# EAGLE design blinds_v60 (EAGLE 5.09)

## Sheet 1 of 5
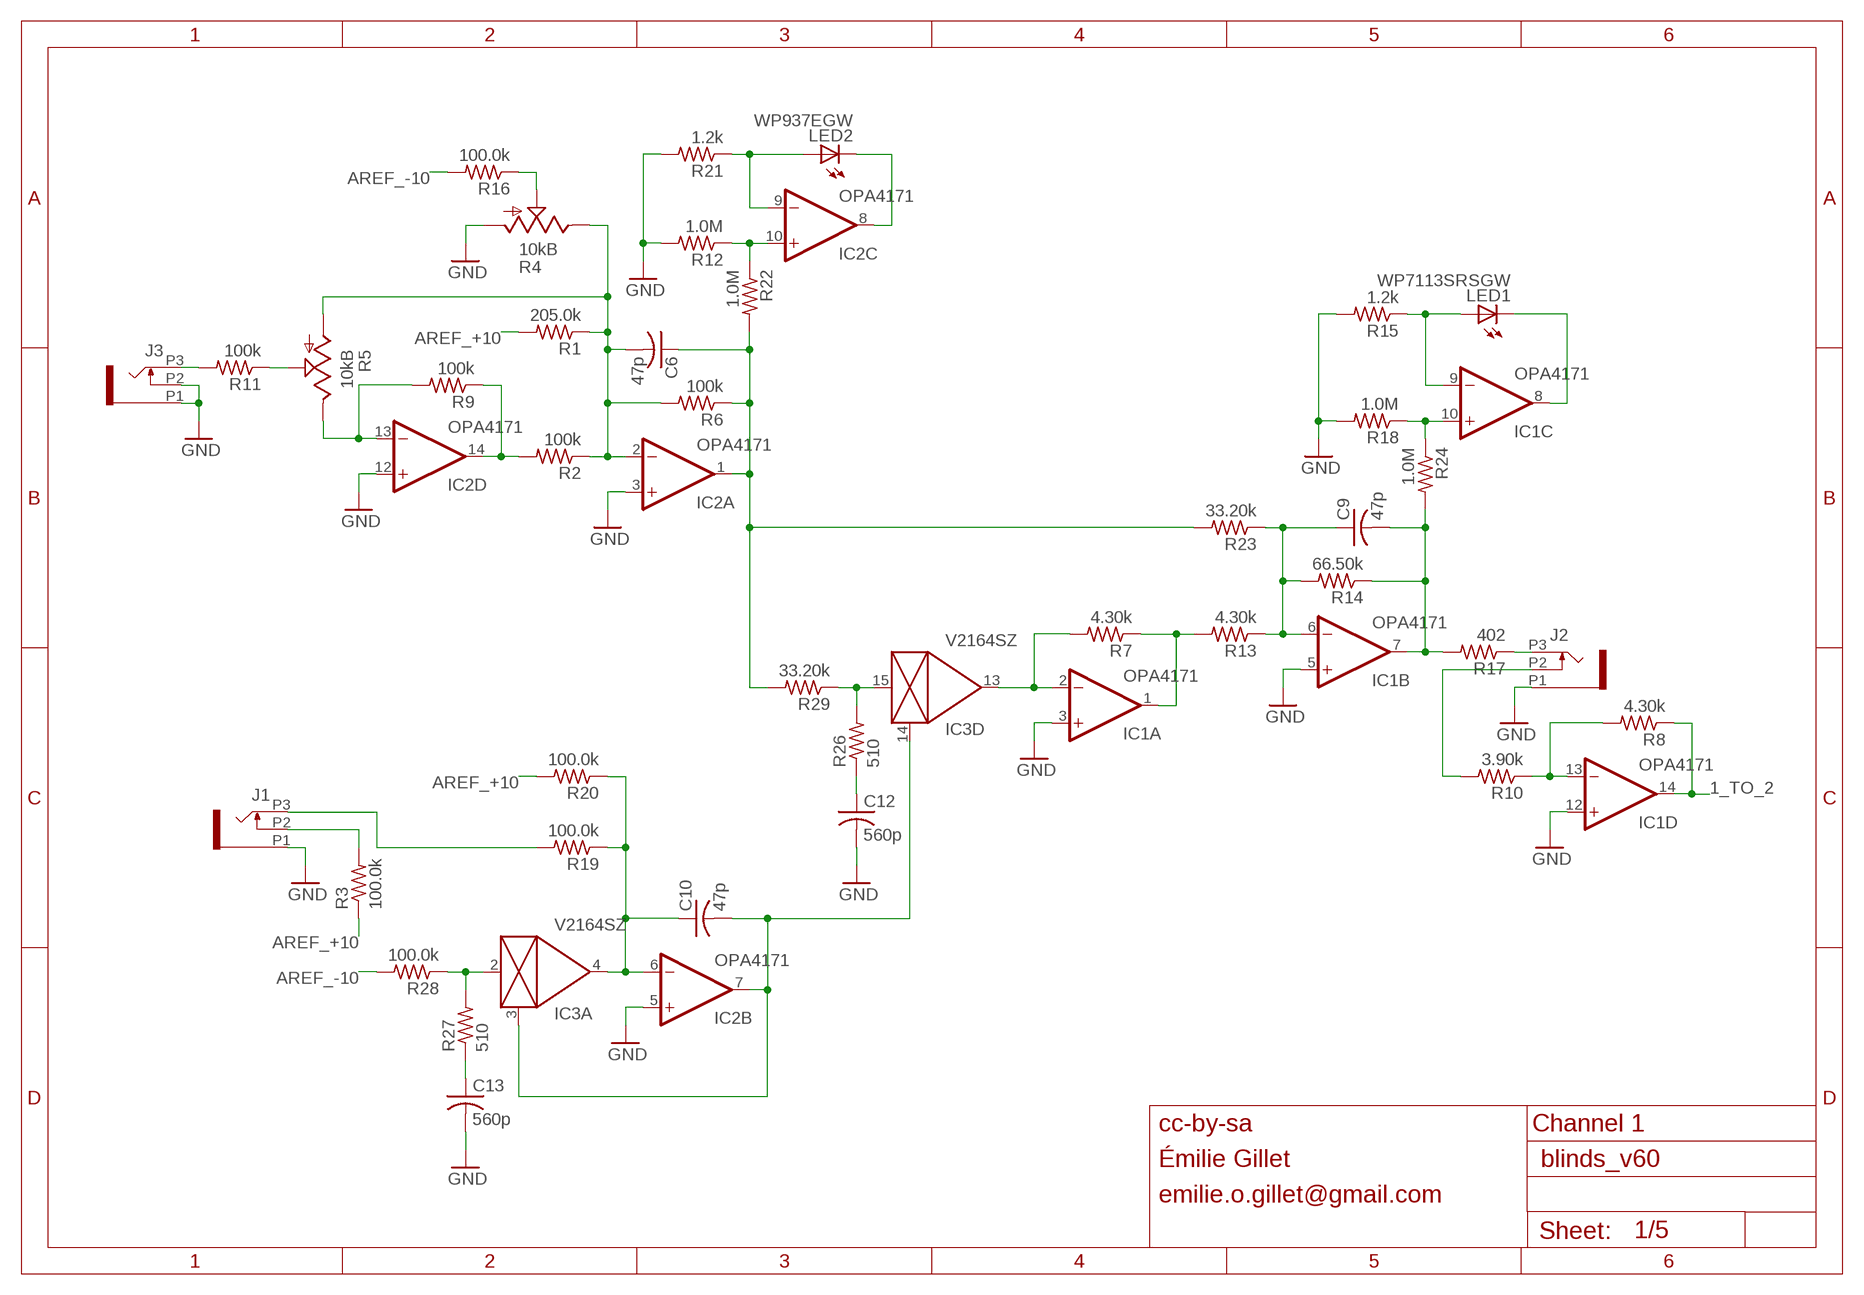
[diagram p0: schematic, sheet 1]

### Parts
C6  47p  C-USC0603  [C0603]
C9  47p  C-USC0603  [C0603]
C10  47p  C-USC0603  [C0603]
C12  560p  C-USC0603  [C0603]
C13  560p  C-USC0603  [C0603]
IC1  OPA4171  TL074PW  [TSSOP14]
IC2  OPA4171  TL074PW  [TSSOP14]
IC3  V2164SZ  SSM2164S  [SOIC16N]
J1  PJ301_THONKICONN6  [WQP_PJ_301M6]
J2  PJ301_THONKICONN6  [WQP_PJ_301M6]
J3  PJ301_THONKICONN6  [WQP_PJ_301M6]
LED1  WP7113SRSGW  LED5MM  [LED5MM]
LED2  WP937EGW  LED3MM  [LED3MM]
R1  205.0k  R-US_R0603  [R0603]
R2  100k  R-US_R0603  [R0603]
R3  100.0k  R-US_R0603  [R0603]
R4  10kB  POT_USVERTICAL_PS  [ALPS_POT_VERTICAL_PS]
R5  10kB  POT_USVERTICAL  [ALPS_POT_VERTICAL]
R6  100k  R-US_R0603  [R0603]
R7  4.30k  R-US_R0603  [R0603]
R8  4.30k  R-US_R0603  [R0603]
R9  100k  R-US_R0603  [R0603]
R10  3.90k  R-US_R0603  [R0603]
R11  100k  R-US_R0603  [R0603]
R12  1.0M  R-US_R0603  [R0603]
R13  4.30k  R-US_R0603  [R0603]
R14  66.50k  R-US_R0603  [R0603]
R15  1.2k  R-US_R0603  [R0603]
R16  100.0k  R-US_R0603  [R0603]
R17  402  R-US_R0603  [R0603]
R18  1.0M  R-US_R0603  [R0603]
R19  100.0k  R-US_R0603  [R0603]
R20  100.0k  R-US_R0603  [R0603]
R21  1.2k  R-US_R0603  [R0603]
R22  1.0M  R-US_R0603  [R0603]
R23  33.20k  R-US_R0603  [R0603]
R24  1.0M  R-US_R0603  [R0603]
R26  510  R-US_R0603  [R0603]
R27  510  R-US_R0603  [R0603]
R28  100.0k  R-US_R0603  [R0603]
R29  33.20k  R-US_R0603  [R0603]

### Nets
1_TO_2: IC1.14(D:OUT) R8.1 ; also sheet 2
AREF_+10: R1.2 R3.1 R20.2 ; also sheet 2,3,4,5
AREF_-10: R16.2 R28.2 ; also sheet 2,3,4,5
CV_IN_1: J3.P3 R11.2
FOO: IC3.2(A:IN) R27.2 R28.1
GAIN_1: C6.1 IC2.1(A:OUT) R6.1 R22.2 R23.2 R29.2
GND: C12.2 C13.2 IC1.3(A:+IN) IC1.5(B:+IN) IC1.12(D:+IN) IC2.3(A:+IN) IC2.5(B:+IN) IC2.12(D:+IN) J1.P1 J2.P1 J3.P1 J3.P2 R4.P$3(A) R12.2 R15.2 R18.2 R21.2 ; also sheet 2,3,4,5
N$2: R4.P$2(S) R16.1
N$3: IC1.2(A:-IN) IC3.13(D:OUT) R7.2
N$4: IC2.8(C:OUT) LED2.K(C)
N$5: IC2.13(D:-IN) R5.P$1(E) R9.2
N$7: J2.P3 R17.1
N$8: IC2.14(D:OUT) R2.2 R9.1
N$9: C6.2 IC2.2(A:-IN) R1.1 R2.1 R4.P$1(E) R5.P$3(A) R6.2
N$10: C9.1 IC1.6(B:-IN) R13.1 R14.2 R23.1
N$14: R5.P$2(S) R11.1
N$15: IC2.9(C:-IN) LED2.A R21.1
N$18: IC1.8(C:OUT) LED1.K(C)
N$19: IC1.9(C:-IN) LED1.A R15.1
N$20: C13.1 R27.1
N$21: J1.P3 R19.2
N$22: IC1.13(D:-IN) R8.2 R10.1
N$25: J2.P2 R10.2
N$47: C12.1 R26.1
N$54: J1.P2 R3.2
N$64: IC1.1(A:OUT) R7.1 R13.2
N$65: C10.1 IC2.6(B:-IN) IC3.4(A:OUT) R19.1 R20.1
N$66: C10.2 IC2.7(B:OUT) IC3.3(A:CTRL) IC3.14(D:CTRL)
N$75: IC3.15(D:IN) R26.2 R29.1
N$96: IC1.10(C:+IN) R18.1 R24.1
N$99: IC2.10(C:+IN) R12.1 R22.1
OUT1: C9.2 IC1.7(B:OUT) R14.1 R17.2 R24.2

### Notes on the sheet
- cc-by-sa | Channel 1
- Émilie Gillet
- emilie.o.gillet@gmail.com

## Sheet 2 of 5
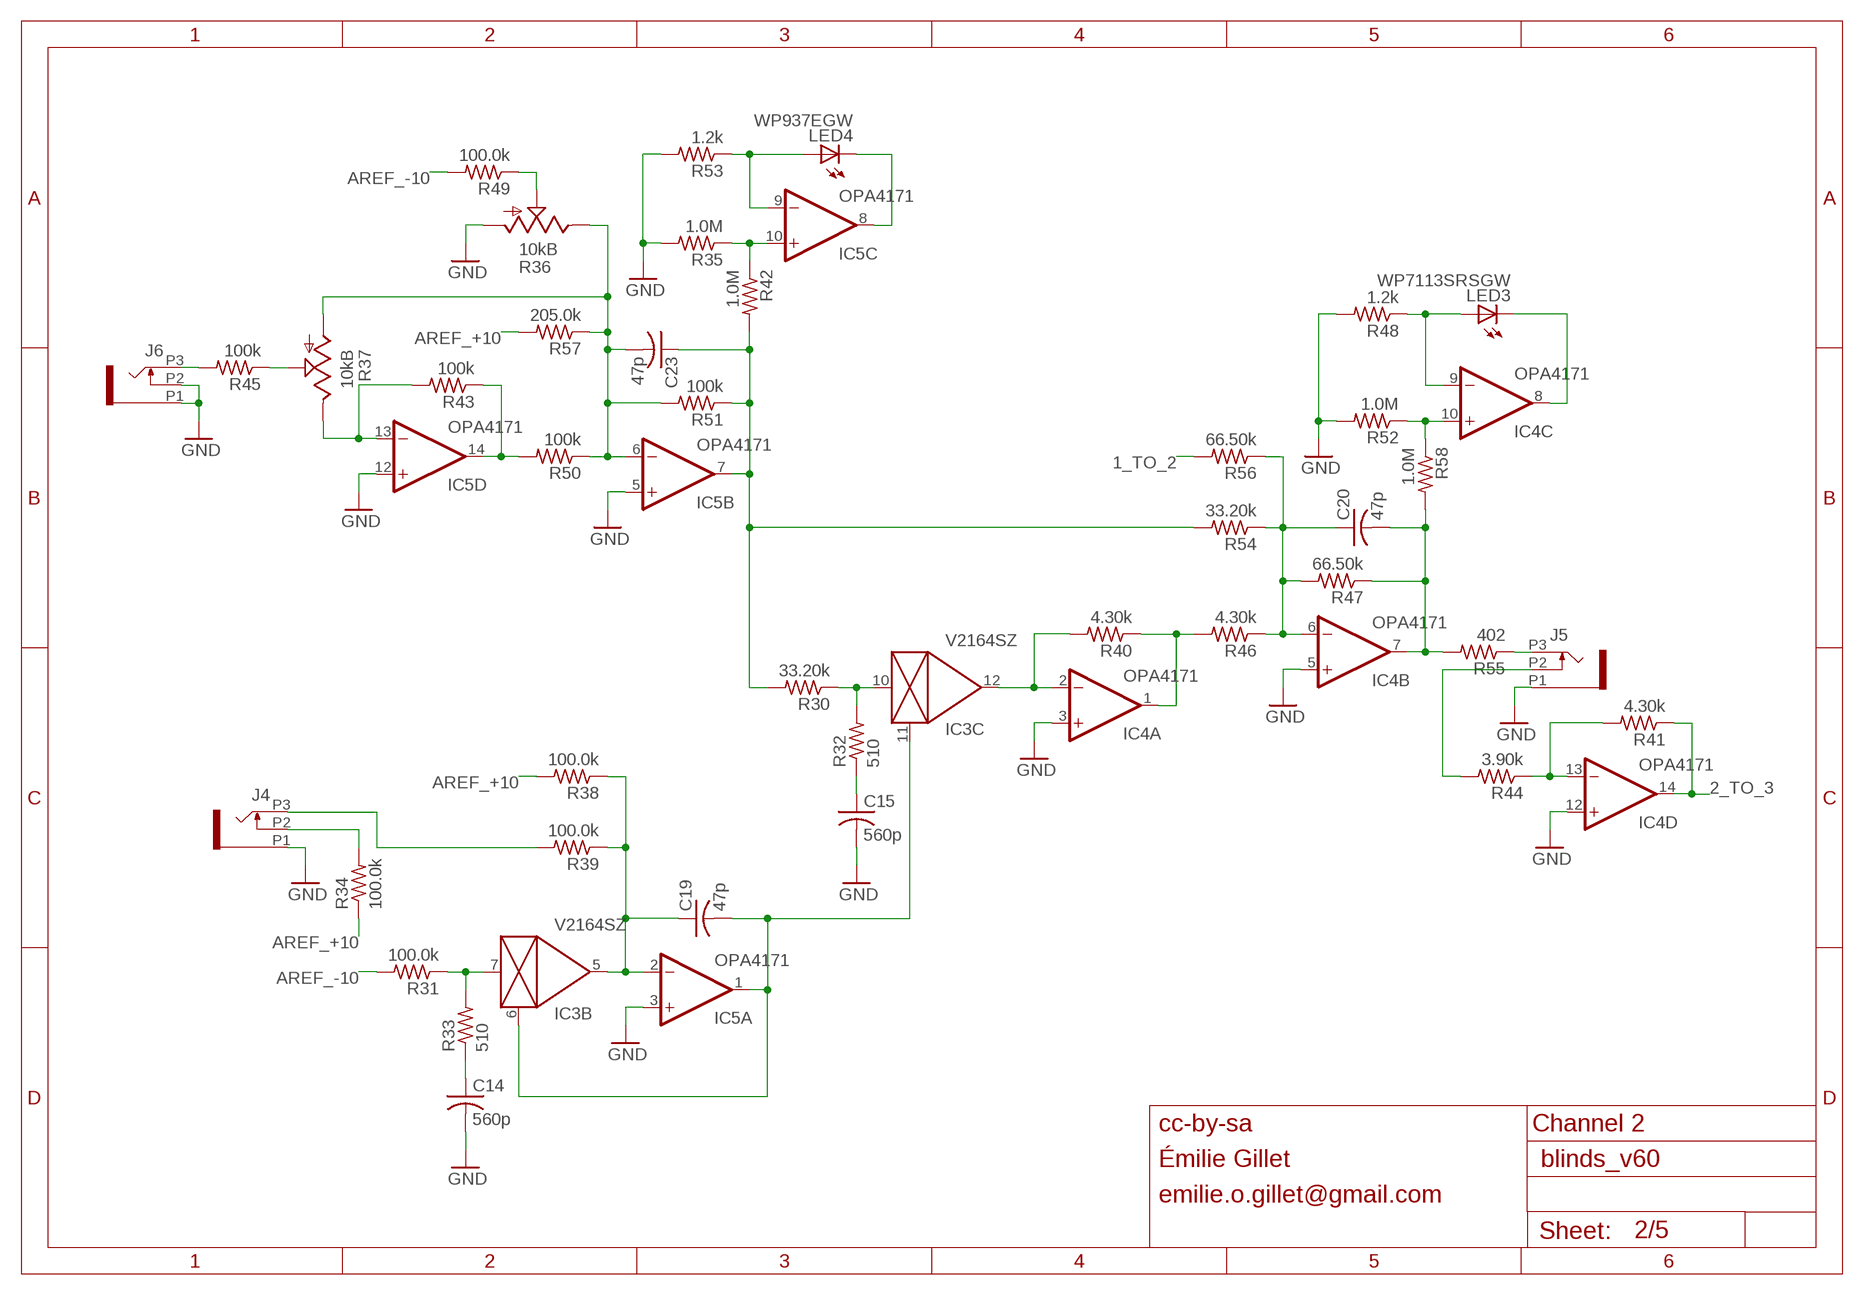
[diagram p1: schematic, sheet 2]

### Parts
C14  560p  C-USC0603  [C0603]
C15  560p  C-USC0603  [C0603]
C19  47p  C-USC0603  [C0603]
C20  47p  C-USC0603  [C0603]
C23  47p  C-USC0603  [C0603]
IC4  OPA4171  TL074PW  [TSSOP14]
IC5  OPA4171  TL074PW  [TSSOP14]
J4  PJ301_THONKICONN6  [WQP_PJ_301M6]
J5  PJ301_THONKICONN6  [WQP_PJ_301M6]
J6  PJ301_THONKICONN6  [WQP_PJ_301M6]
LED3  WP7113SRSGW  LED5MM  [LED5MM]
LED4  WP937EGW  LED3MM  [LED3MM]
R30  33.20k  R-US_R0603  [R0603]
R31  100.0k  R-US_R0603  [R0603]
R32  510  R-US_R0603  [R0603]
R33  510  R-US_R0603  [R0603]
R34  100.0k  R-US_R0603  [R0603]
R35  1.0M  R-US_R0603  [R0603]
R36  10kB  POT_USVERTICAL_PS  [ALPS_POT_VERTICAL_PS]
R37  10kB  POT_USVERTICAL  [ALPS_POT_VERTICAL]
R38  100.0k  R-US_R0603  [R0603]
R39  100.0k  R-US_R0603  [R0603]
R40  4.30k  R-US_R0603  [R0603]
R41  4.30k  R-US_R0603  [R0603]
R42  1.0M  R-US_R0603  [R0603]
R43  100k  R-US_R0603  [R0603]
R44  3.90k  R-US_R0603  [R0603]
R45  100k  R-US_R0603  [R0603]
R46  4.30k  R-US_R0603  [R0603]
R47  66.50k  R-US_R0603  [R0603]
R48  1.2k  R-US_R0603  [R0603]
R49  100.0k  R-US_R0603  [R0603]
R50  100k  R-US_R0603  [R0603]
R51  100k  R-US_R0603  [R0603]
R52  1.0M  R-US_R0603  [R0603]
R53  1.2k  R-US_R0603  [R0603]
R54  33.20k  R-US_R0603  [R0603]
R55  402  R-US_R0603  [R0603]
R56  66.50k  R-US_R0603  [R0603]
R57  205.0k  R-US_R0603  [R0603]
R58  1.0M  R-US_R0603  [R0603]

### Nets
1_TO_2: R56.2 ; also sheet 1
2_TO_3: IC4.14(D:OUT) R41.1 ; also sheet 3
AREF_+10: R34.1 R38.2 R57.2 ; also sheet 1,3,4,5
AREF_-10: R31.2 R49.2 ; also sheet 1,3,4,5
FOO1: IC3.7(B:IN) R31.1 R33.2
GAIN_2: C23.1 IC5.7(B:OUT) R30.2 R42.2 R51.1 R54.2
GND: C14.2 C15.2 IC4.3(A:+IN) IC4.5(B:+IN) IC4.12(D:+IN) IC5.3(A:+IN) IC5.5(B:+IN) IC5.12(D:+IN) J4.P1 J5.P1 J6.P1 J6.P2 R35.2 R36.P$3(A) R48.2 R52.2 R53.2 ; also sheet 1,3,4,5
N$6: J5.P3 R55.1
N$17: C15.1 R32.1
N$24: IC3.10(C:IN) R30.1 R32.2
N$26: IC3.12(C:OUT) IC4.2(A:-IN) R40.2
N$27: C20.1 IC4.6(B:-IN) R46.1 R47.2 R54.1 R56.1
N$28: J6.P3 R45.2
N$29: IC5.13(D:-IN) R37.P$1(E) R43.2
N$30: IC5.14(D:OUT) R43.1 R50.2
N$31: C23.2 IC5.6(B:-IN) R36.P$1(E) R37.P$3(A) R50.1 R51.2 R57.1
N$32: R36.P$2(S) R49.1
N$33: IC5.8(C:OUT) LED4.K(C)
N$34: IC5.9(C:-IN) LED4.A R53.1
N$35: IC4.8(C:OUT) LED3.K(C)
N$36: IC4.9(C:-IN) LED3.A R48.1
N$37: IC4.13(D:-IN) R41.2 R44.1
N$38: J5.P2 R44.2
N$39: IC4.1(A:OUT) R40.1 R46.2
N$40: R37.P$2(S) R45.1
N$41: C14.1 R33.1
N$42: C19.1 IC3.5(B:OUT) IC5.2(A:-IN) R38.1 R39.1
N$43: C19.2 IC3.6(B:CTRL) IC3.11(C:CTRL) IC5.1(A:OUT)
N$44: J4.P3 R39.2
N$87: J4.P2 R34.2
N$97: IC4.10(C:+IN) R52.1 R58.1
N$103: IC5.10(C:+IN) R35.1 R42.1
OUT2: C20.2 IC4.7(B:OUT) R47.1 R55.2 R58.2

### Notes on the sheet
- cc-by-sa | Channel 2
- Émilie Gillet
- emilie.o.gillet@gmail.com

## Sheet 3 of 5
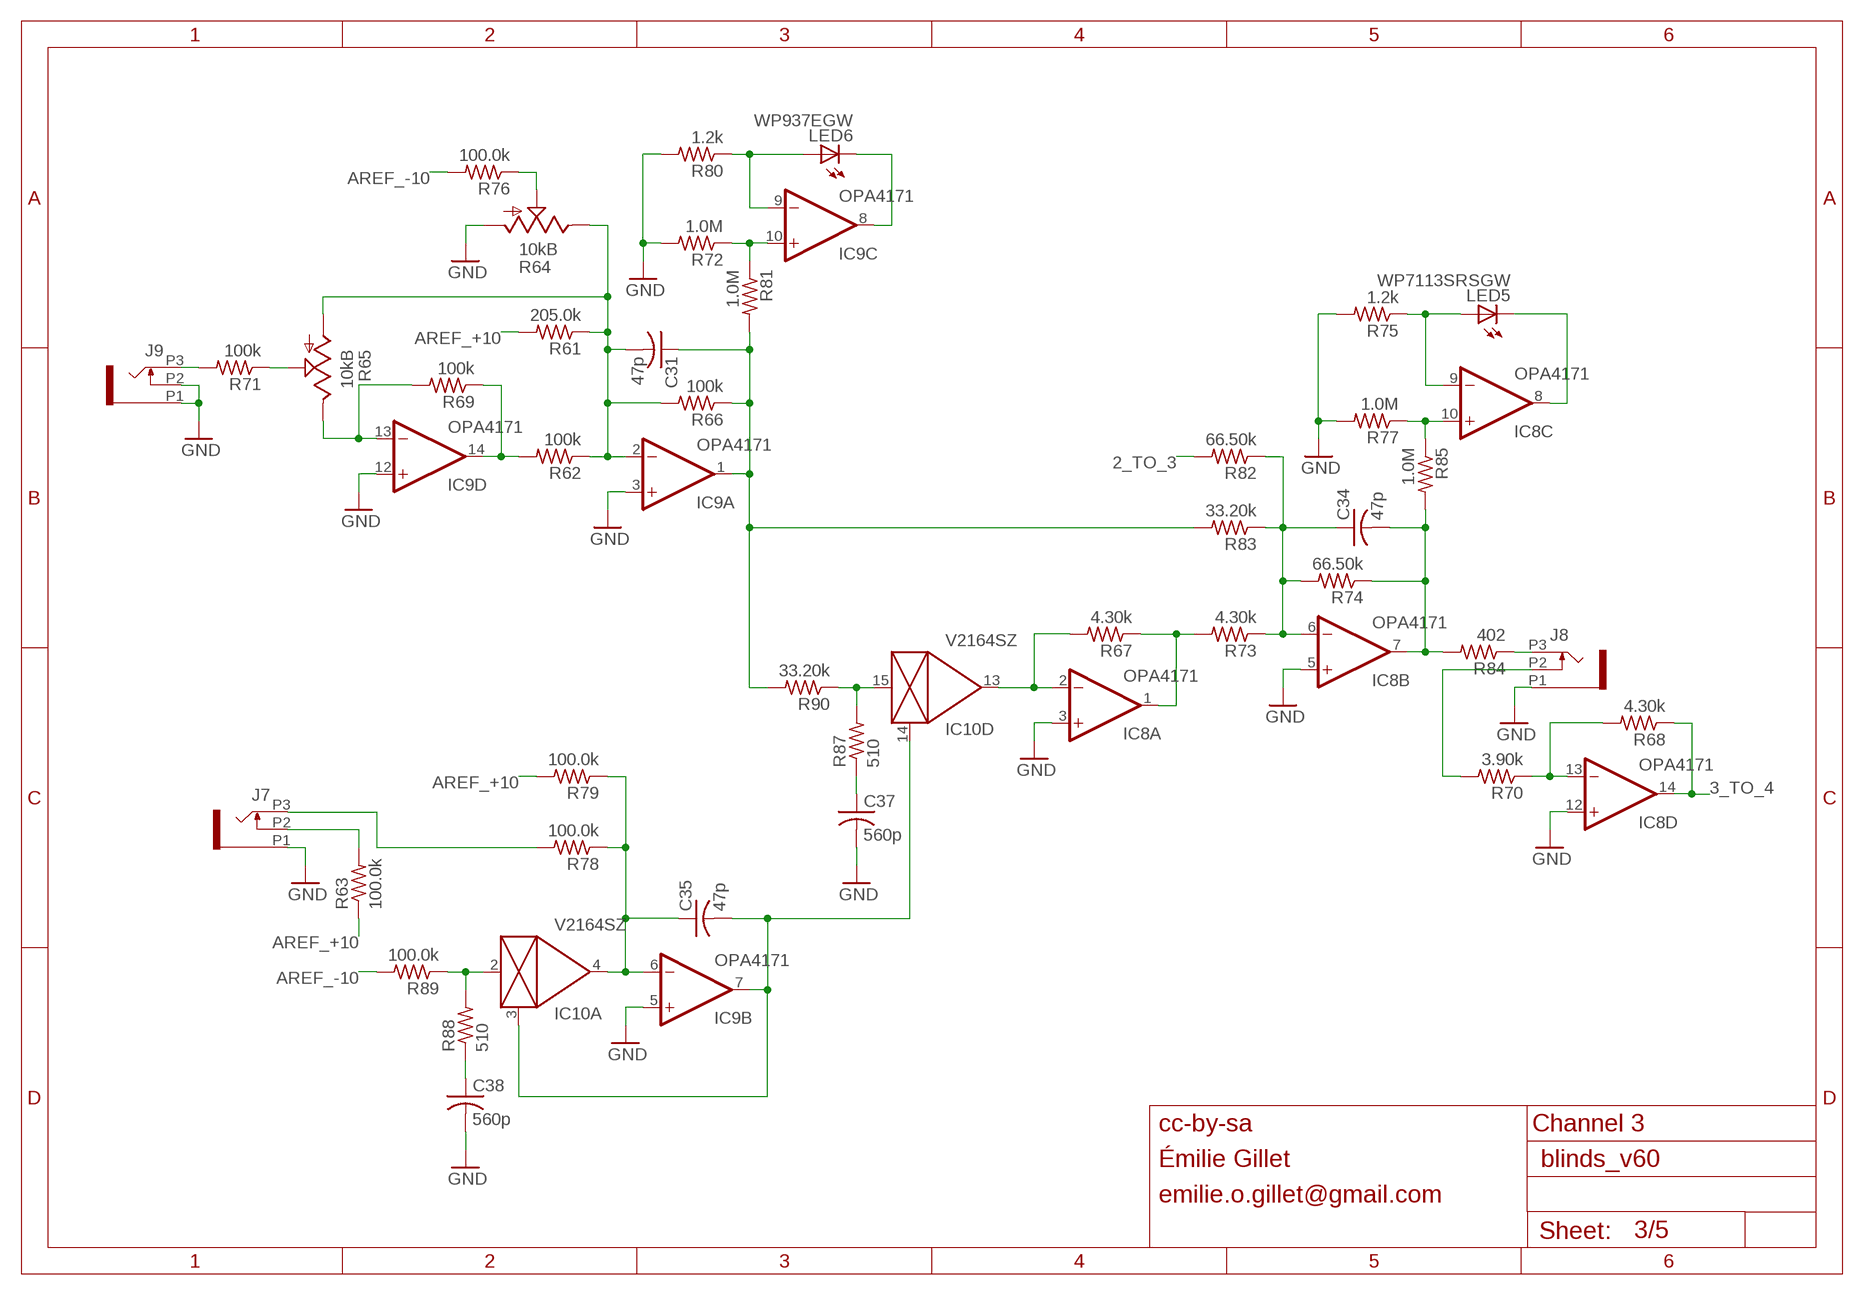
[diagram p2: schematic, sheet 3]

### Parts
C31  47p  C-USC0603  [C0603]
C34  47p  C-USC0603  [C0603]
C35  47p  C-USC0603  [C0603]
C37  560p  C-USC0603  [C0603]
C38  560p  C-USC0603  [C0603]
IC8  OPA4171  TL074PW  [TSSOP14]
IC9  OPA4171  TL074PW  [TSSOP14]
IC10  V2164SZ  SSM2164S  [SOIC16N]
J7  PJ301_THONKICONN6  [WQP_PJ_301M6]
J8  PJ301_THONKICONN6  [WQP_PJ_301M6]
J9  PJ301_THONKICONN6  [WQP_PJ_301M6]
LED5  WP7113SRSGW  LED5MM  [LED5MM]
LED6  WP937EGW  LED3MM  [LED3MM]
R61  205.0k  R-US_R0603  [R0603]
R62  100k  R-US_R0603  [R0603]
R63  100.0k  R-US_R0603  [R0603]
R64  10kB  POT_USVERTICAL_PS  [ALPS_POT_VERTICAL_PS]
R65  10kB  POT_USVERTICAL  [ALPS_POT_VERTICAL]
R66  100k  R-US_R0603  [R0603]
R67  4.30k  R-US_R0603  [R0603]
R68  4.30k  R-US_R0603  [R0603]
R69  100k  R-US_R0603  [R0603]
R70  3.90k  R-US_R0603  [R0603]
R71  100k  R-US_R0603  [R0603]
R72  1.0M  R-US_R0603  [R0603]
R73  4.30k  R-US_R0603  [R0603]
R74  66.50k  R-US_R0603  [R0603]
R75  1.2k  R-US_R0603  [R0603]
R76  100.0k  R-US_R0603  [R0603]
R77  1.0M  R-US_R0603  [R0603]
R78  100.0k  R-US_R0603  [R0603]
R79  100.0k  R-US_R0603  [R0603]
R80  1.2k  R-US_R0603  [R0603]
R81  1.0M  R-US_R0603  [R0603]
R82  66.50k  R-US_R0603  [R0603]
R83  33.20k  R-US_R0603  [R0603]
R84  402  R-US_R0603  [R0603]
R85  1.0M  R-US_R0603  [R0603]
R87  510  R-US_R0603  [R0603]
R88  510  R-US_R0603  [R0603]
R89  100.0k  R-US_R0603  [R0603]
R90  33.20k  R-US_R0603  [R0603]

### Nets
2_TO_3: R82.2 ; also sheet 2
3_TO_4: IC8.14(D:OUT) R68.1 ; also sheet 4
AREF_+10: R61.2 R63.1 R79.2 ; also sheet 1,2,4,5
AREF_-10: R76.2 R89.2 ; also sheet 1,2,4,5
FOO2: IC10.2(A:IN) R88.2 R89.1
GAIN_3: C31.1 IC9.1(A:OUT) R66.1 R81.2 R83.2 R90.2
GND: C37.2 C38.2 IC8.3(A:+IN) IC8.5(B:+IN) IC8.12(D:+IN) IC9.3(A:+IN) IC9.5(B:+IN) IC9.12(D:+IN) J7.P1 J8.P1 J9.P1 J9.P2 R64.P$3(A) R72.2 R75.2 R77.2 R80.2 ; also sheet 1,2,4,5
N$23: J8.P3 R84.1
N$45: C37.1 R87.1
N$46: IC10.15(D:IN) R87.2 R90.1
N$48: IC8.2(A:-IN) IC10.13(D:OUT) R67.2
N$49: C34.1 IC8.6(B:-IN) R73.1 R74.2 R82.1 R83.1
N$50: J9.P3 R71.2
N$51: IC9.13(D:-IN) R65.P$1(E) R69.2
N$52: IC9.14(D:OUT) R62.2 R69.1
N$53: C31.2 IC9.2(A:-IN) R61.1 R62.1 R64.P$1(E) R65.P$3(A) R66.2
N$55: R64.P$2(S) R76.1
N$56: IC9.8(C:OUT) LED6.K(C)
N$57: IC9.9(C:-IN) LED6.A R80.1
N$58: IC8.8(C:OUT) LED5.K(C)
N$59: IC8.9(C:-IN) LED5.A R75.1
N$60: IC8.13(D:-IN) R68.2 R70.1
N$61: J8.P2 R70.2
N$62: IC8.1(A:OUT) R67.1 R73.2
N$63: C38.1 R88.1
N$67: C35.1 IC9.6(B:-IN) IC10.4(A:OUT) R78.1 R79.1
N$68: C35.2 IC9.7(B:OUT) IC10.3(A:CTRL) IC10.14(D:CTRL)
N$70: R65.P$2(S) R71.1
N$93: J7.P3 R78.2
N$94: J7.P2 R63.2
N$98: IC8.10(C:+IN) R77.1 R85.1
N$102: IC9.10(C:+IN) R72.1 R81.1
OUT3: C34.2 IC8.7(B:OUT) R74.1 R84.2 R85.2

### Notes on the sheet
- cc-by-sa | Channel 3
- Émilie Gillet
- emilie.o.gillet@gmail.com

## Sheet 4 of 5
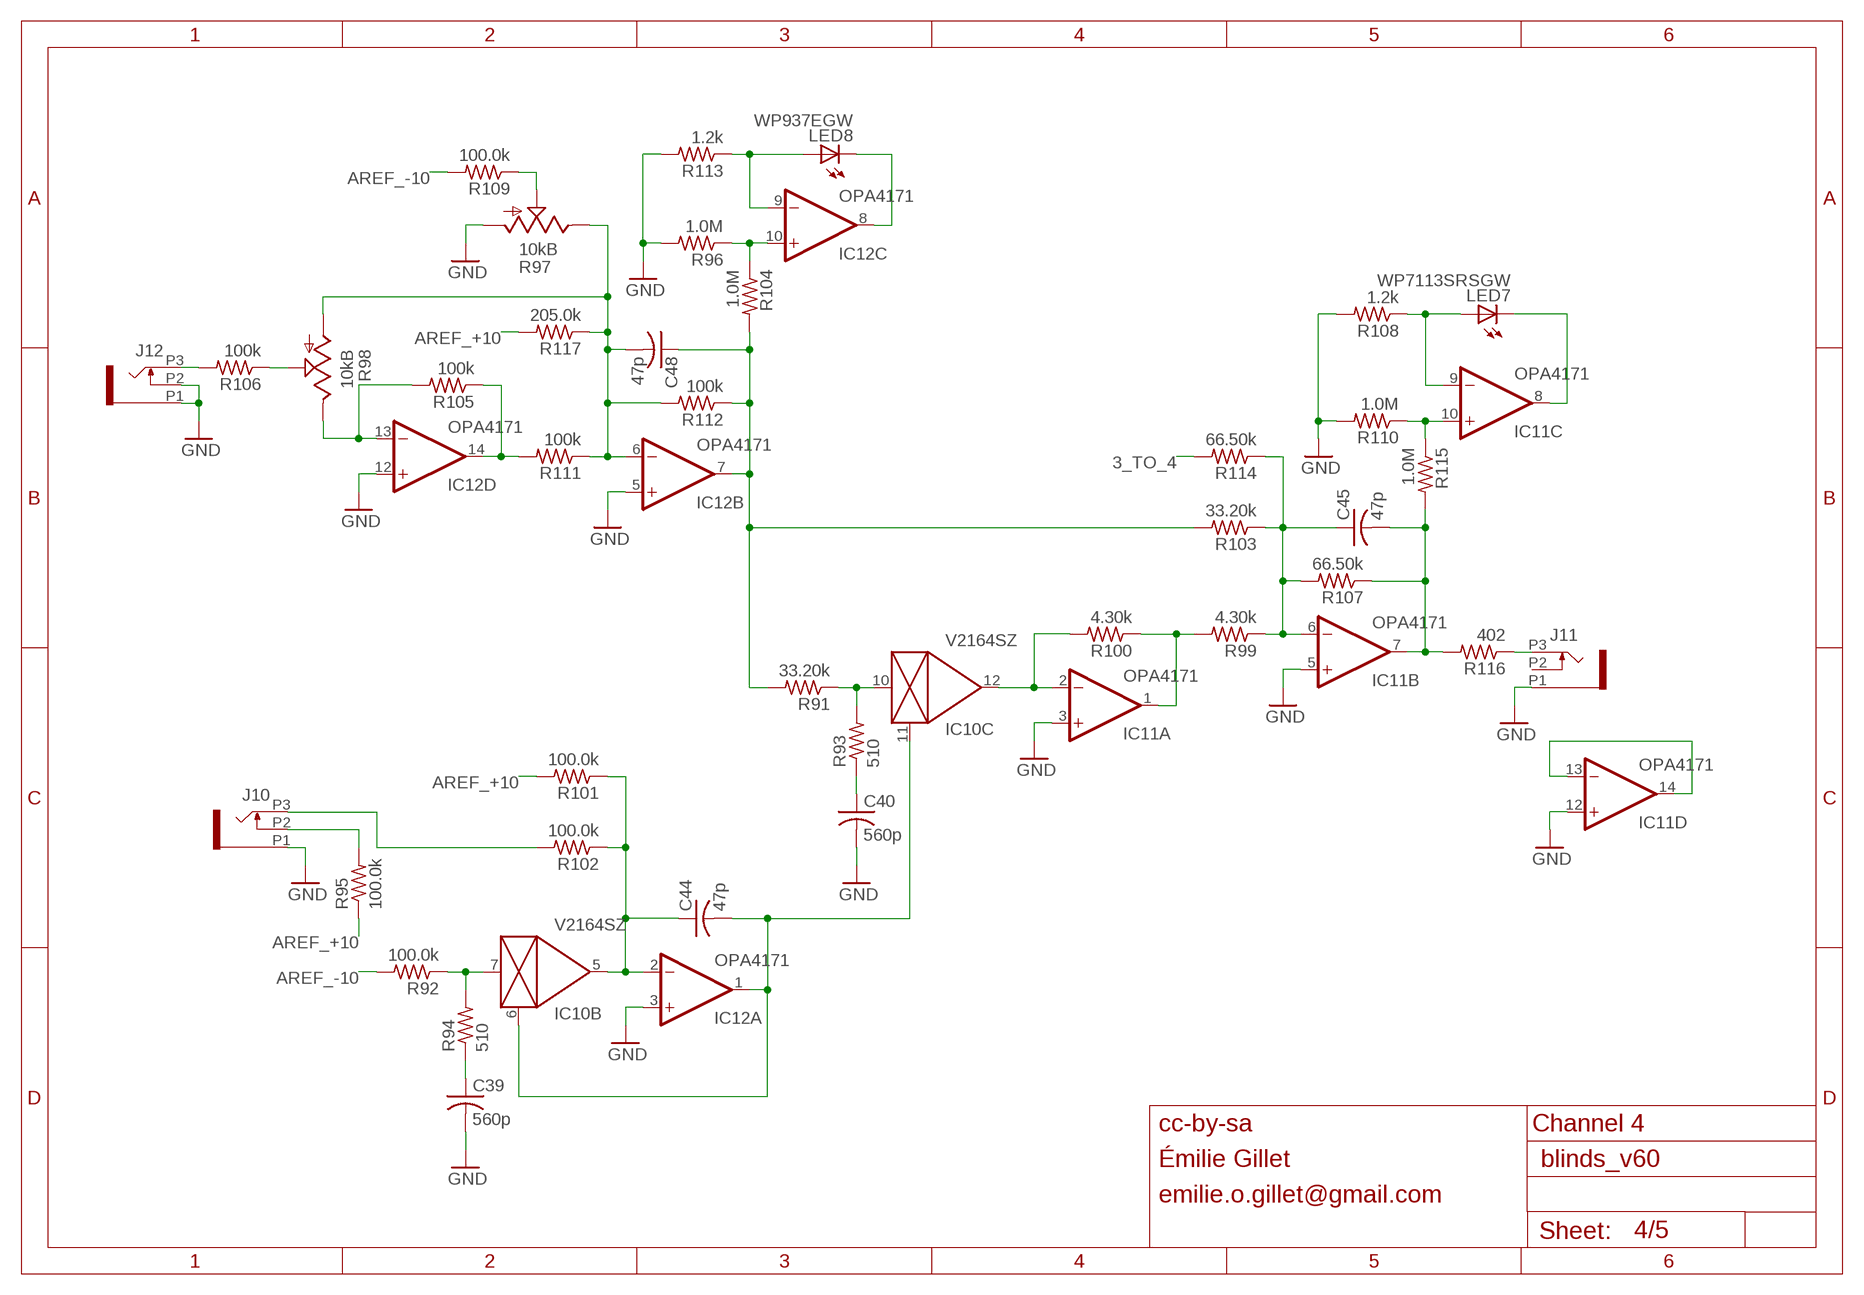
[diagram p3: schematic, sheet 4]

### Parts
C39  560p  C-USC0603  [C0603]
C40  560p  C-USC0603  [C0603]
C44  47p  C-USC0603  [C0603]
C45  47p  C-USC0603  [C0603]
C48  47p  C-USC0603  [C0603]
IC11  OPA4171  TL074PW  [TSSOP14]
IC12  OPA4171  TL074PW  [TSSOP14]
J10  PJ301_THONKICONN6  [WQP_PJ_301M6]
J11  PJ301_THONKICONN6  [WQP_PJ_301M6]
J12  PJ301_THONKICONN6  [WQP_PJ_301M6]
LED7  WP7113SRSGW  LED5MM  [LED5MM]
LED8  WP937EGW  LED3MM  [LED3MM]
R91  33.20k  R-US_R0603  [R0603]
R92  100.0k  R-US_R0603  [R0603]
R93  510  R-US_R0603  [R0603]
R94  510  R-US_R0603  [R0603]
R95  100.0k  R-US_R0603  [R0603]
R96  1.0M  R-US_R0603  [R0603]
R97  10kB  POT_USVERTICAL_PS  [ALPS_POT_VERTICAL_PS]
R98  10kB  POT_USVERTICAL  [ALPS_POT_VERTICAL]
R99  4.30k  R-US_R0603  [R0603]
R100  4.30k  R-US_R0603  [R0603]
R101  100.0k  R-US_R0603  [R0603]
R102  100.0k  R-US_R0603  [R0603]
R103  33.20k  R-US_R0603  [R0603]
R104  1.0M  R-US_R0603  [R0603]
R105  100k  R-US_R0603  [R0603]
R106  100k  R-US_R0603  [R0603]
R107  66.50k  R-US_R0603  [R0603]
R108  1.2k  R-US_R0603  [R0603]
R109  100.0k  R-US_R0603  [R0603]
R110  1.0M  R-US_R0603  [R0603]
R111  100k  R-US_R0603  [R0603]
R112  100k  R-US_R0603  [R0603]
R113  1.2k  R-US_R0603  [R0603]
R114  66.50k  R-US_R0603  [R0603]
R115  1.0M  R-US_R0603  [R0603]
R116  402  R-US_R0603  [R0603]
R117  205.0k  R-US_R0603  [R0603]

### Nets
3_TO_4: R114.2 ; also sheet 3
AREF_+5: IC11.13(D:-IN) IC11.14(D:OUT)
AREF_+10: R95.1 R101.2 R117.2 ; also sheet 1,2,3,5
AREF_-10: R92.2 R109.2 ; also sheet 1,2,3,5
FOO3: IC10.7(B:IN) R92.1 R94.2
GAIN_4: C48.1 IC12.7(B:OUT) R91.2 R103.2 R104.2 R112.1
GND: C39.2 C40.2 IC11.3(A:+IN) IC11.5(B:+IN) IC11.12(D:+IN) IC12.3(A:+IN) IC12.5(B:+IN) IC12.12(D:+IN) J10.P1 J11.P1 J12.P1 J12.P2 R96.2 R97.P$3(A) R108.2 R110.2 R113.2 ; also sheet 1,2,3,5
N$69: J10.P3 R102.2
N$71: J11.P3 R116.1
N$72: C40.1 R93.1
N$73: IC10.10(C:IN) R91.1 R93.2
N$74: IC10.12(C:OUT) IC11.2(A:-IN) R100.2
N$76: C45.1 IC11.6(B:-IN) R99.1 R103.1 R107.2 R114.1
N$77: J12.P3 R106.2
N$78: IC12.13(D:-IN) R98.P$1(E) R105.2
N$79: IC12.14(D:OUT) R105.1 R111.2
N$80: C48.2 IC12.6(B:-IN) R97.P$1(E) R98.P$3(A) R111.1 R112.2 R117.1
N$81: R97.P$2(S) R109.1
N$82: IC12.8(C:OUT) LED8.K(C)
N$83: IC12.9(C:-IN) LED8.A R113.1
N$84: IC11.8(C:OUT) LED7.K(C)
N$85: IC11.9(C:-IN) LED7.A R108.1
N$88: IC11.1(A:OUT) R99.2 R100.1
N$89: R98.P$2(S) R106.1
N$90: C39.1 R94.1
N$91: C44.1 IC10.5(B:OUT) IC12.2(A:-IN) R101.1 R102.1
N$92: C44.2 IC10.6(B:CTRL) IC10.11(C:CTRL) IC12.1(A:OUT)
N$95: J10.P2 R95.2
N$100: IC11.10(C:+IN) R110.1 R115.1
N$101: IC12.10(C:+IN) R96.1 R104.1
OUT4: C45.2 IC11.7(B:OUT) R107.1 R115.2 R116.2
Unconnected: J11.P2

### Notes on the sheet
- cc-by-sa | Channel 4
- Émilie Gillet
- emilie.o.gillet@gmail.com

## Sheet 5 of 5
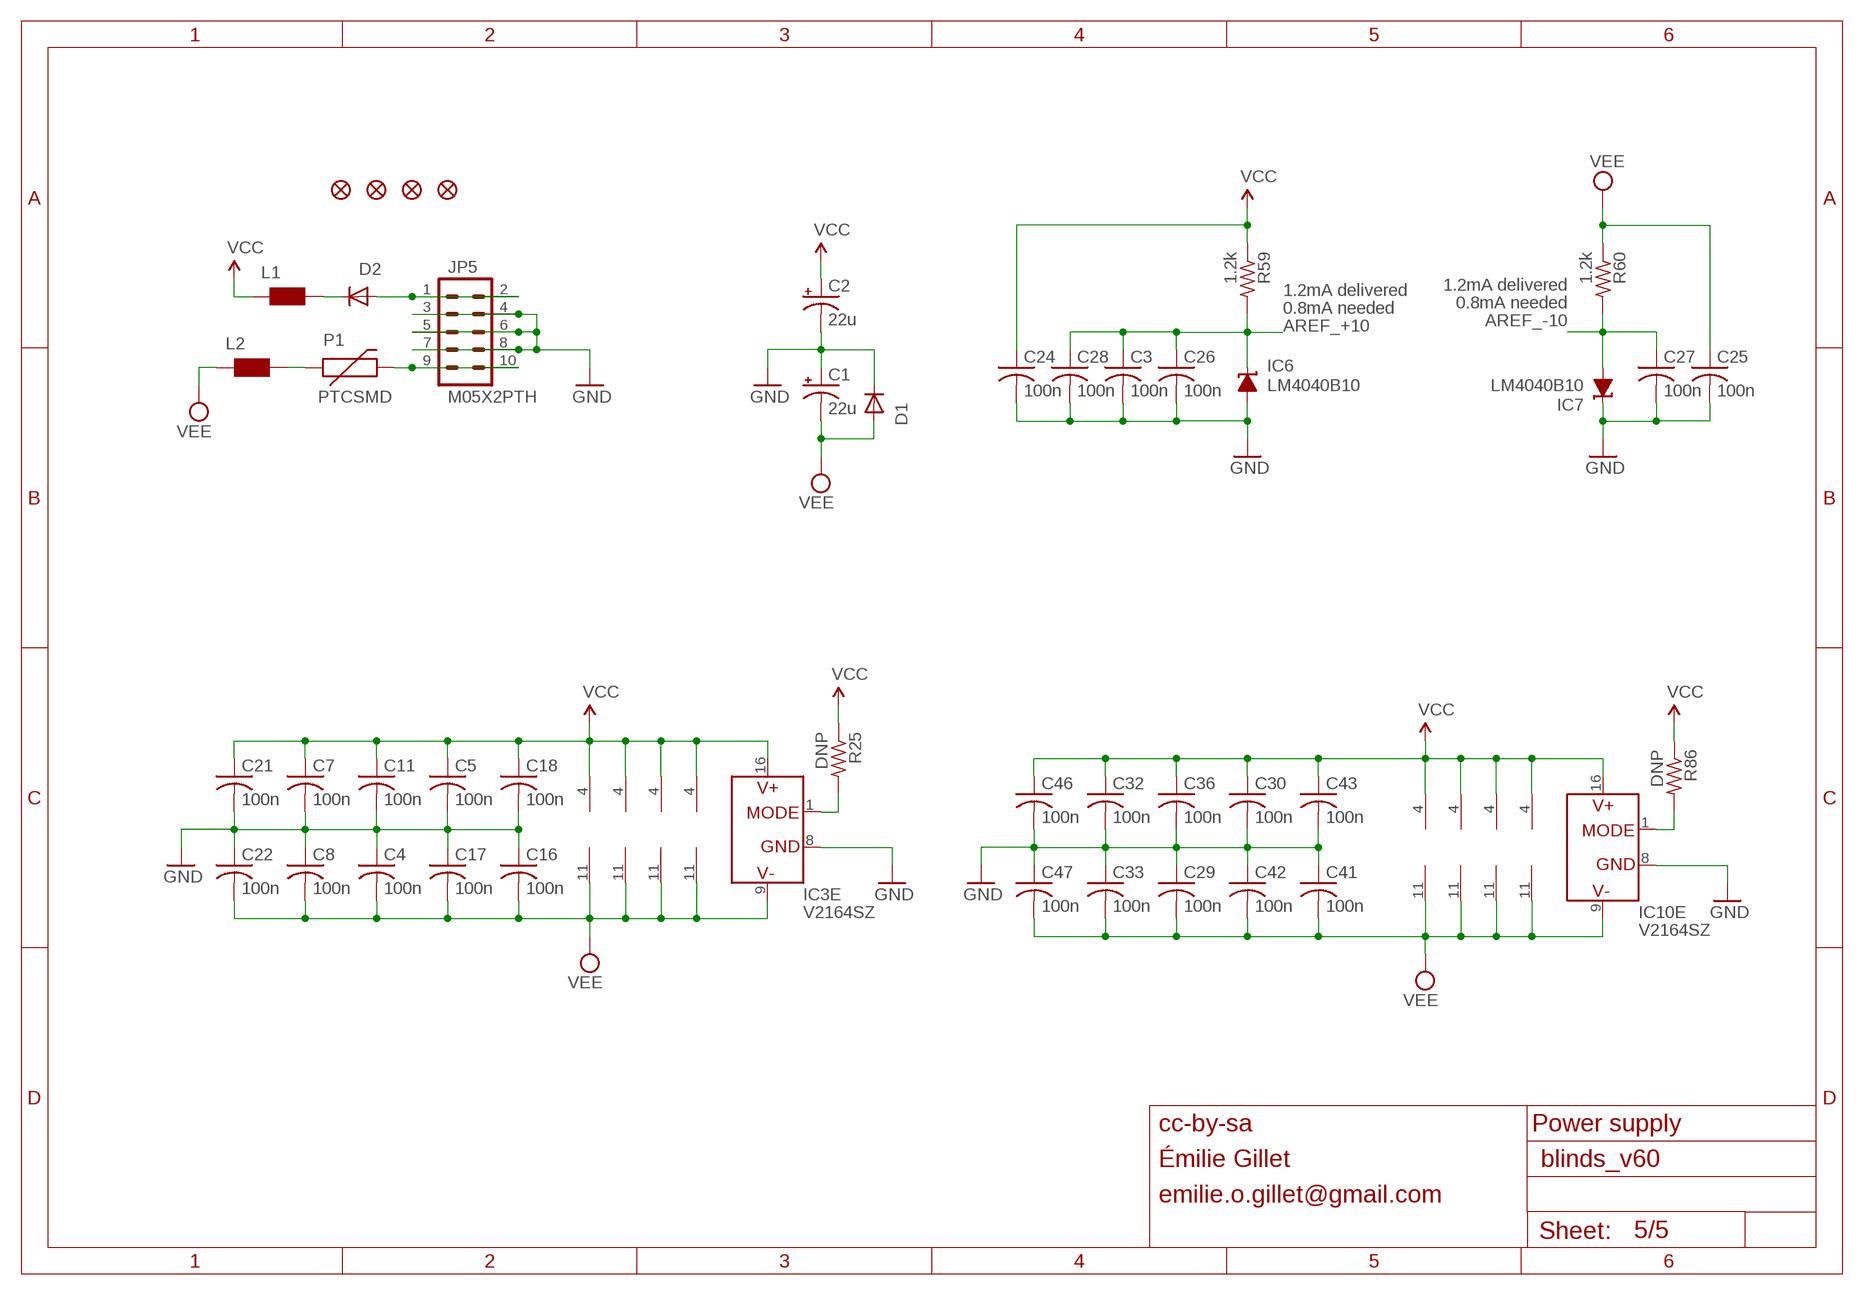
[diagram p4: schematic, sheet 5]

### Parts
C1  22u  CPOL-USC  [PANASONIC_C]
C2  22u  CPOL-USC  [PANASONIC_C]
C3  100n  C-USC0603  [C0603]
C4  100n  C-USC0603  [C0603]
C5  100n  C-USC0603  [C0603]
C7  100n  C-USC0603  [C0603]
C8  100n  C-USC0603  [C0603]
C11  100n  C-USC0603  [C0603]
C16  100n  C-USC0603  [C0603]
C17  100n  C-USC0603  [C0603]
C18  100n  C-USC0603  [C0603]
C21  100n  C-USC0603  [C0603]
C22  100n  C-USC0603  [C0603]
C24  100n  C-USC0603  [C0603]
C25  100n  C-USC0603  [C0603]
C26  100n  C-USC0603  [C0603]
C27  100n  C-USC0603  [C0603]
C28  100n  C-USC0603  [C0603]
C29  100n  C-USC0603  [C0603]
C30  100n  C-USC0603  [C0603]
C32  100n  C-USC0603  [C0603]
C33  100n  C-USC0603  [C0603]
C36  100n  C-USC0603  [C0603]
C41  100n  C-USC0603  [C0603]
C42  100n  C-USC0603  [C0603]
C43  100n  C-USC0603  [C0603]
C46  100n  C-USC0603  [C0603]
C47  100n  C-USC0603  [C0603]
D1  1N5819HW  DIODE-SOD123  [SOD123]
D2  1N5819HW  DIODE-SOD123  [SOD123]
IC6  LM4040B10  LM4041B12DBZ  [DBZ_R-PDSO-G3]
IC7  LM4040B10  LM4041B12DBZ  [DBZ_R-PDSO-G3]
JP1  FIDUCIAL1X2  [FIDUCIAL-1X2]
JP2  FIDUCIAL1X2  [FIDUCIAL-1X2]
JP3  FIDUCIAL1X2  [FIDUCIAL-1X2]
JP4  FIDUCIAL1X2  [FIDUCIAL-1X2]
JP5  M05X2PTH  [AVR_ICSP]
L1  WE-CBF_0603  [0603]
L2  WE-CBF_0603  [0603]
P1  PTCSMD  [PTC-1206]
R25  DNP  R-US_R0603  [R0603]
R59  1.2k  R-US_R0603  [R0603]
R60  1.2k  R-US_R0603  [R0603]
R86  DNP  R-US_R0603  [R0603]

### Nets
AREF_+10: C3.1 C26.1 C28.1 IC6.1(C) R59.2 ; also sheet 1,2,3,4
AREF_-10: C27.1 IC7.2(A) R60.2 ; also sheet 1,2,3,4
GND: C1.+ C2.- C3.2 C4.1 C5.2 C7.2 C8.1 C11.2 C16.1 C17.1 C18.2 C21.2 C22.1 C24.2 C25.2 C26.2 C27.2 C28.2 C29.1 C30.2 C32.2 C33.1 C36.2 C41.1 C42.1 C43.2 C46.2 C47.1 D1.C IC3.8(E:GND) IC6.2(A) IC7.1(C) IC10.8(E:GND) JP5.3 JP5.4 JP5.5 JP5.6 JP5.7 JP5.8 ; also sheet 1,2,3,4
N$1: IC3.1(E:MODE) R25.2
N$11: D2.A JP5.1 JP5.2
N$12: JP5.9 JP5.10 P1.2
N$13: L2.2 P1.1
N$16: D2.C L1.2
N$86: IC10.1(E:MODE) R86.2
VCC: C2.+ C5.1 C7.1 C11.1 C18.1 C21.1 C24.1 C30.1 C32.1 C36.1 C43.1 C46.1 IC1.4(P:V+) IC2.4(P:V+) IC3.16(E:V+) IC4.4(P:V+) IC5.4(P:V+) IC8.4(P:V+) IC9.4(P:V+) IC10.16(E:V+) IC11.4(P:V+) IC12.4(P:V+) L1.1 R25.1 R59.1 R86.1
VEE: C1.- C4.2 C8.2 C16.2 C17.2 C22.2 C25.1 C29.2 C33.2 C41.2 C42.2 C47.2 D1.A IC1.11(P:V-) IC2.11(P:V-) IC3.9(E:V-) IC4.11(P:V-) IC5.11(P:V-) IC8.11(P:V-) IC9.11(P:V-) IC10.9(E:V-) IC11.11(P:V-) IC12.11(P:V-) L2.1 R60.1

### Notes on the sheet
- 1.2mA delivered
- 1.2mA delivered | 0.8mA needed
- 0.8mA needed
- cc-by-sa | Power supply
- Émilie Gillet
- emilie.o.gillet@gmail.com

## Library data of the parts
C1 C2 = rcl:CPOL-US: POLARIZED CAPACITOR, American symbol
C3-C48 = rcl:C-US: CAPACITOR, American symbol
D1 D2 = diode:DIODE-: DIODE
IC1 IC2 IC4 IC5 IC8 IC9 IC11 IC12 = linear:TL074: OP AMP
IC3 IC10 = ssm2164:SSM2164
IC6 IC7 = texas:LM4041: PRECISION MICROPOWER SHUNT VOLTAGE REFERENCE
J1-J12 = og-pj301:PJ301_THONKICONN
JP1-JP4 = SparkFun:FIDUCIAL: Fiducial Alignment Points
JP5 = og-header:M05X2: Header 5x2 Standard 10-pin dual row 0.1" header. Commonly used with AVR-ISP. Use with Spark Fun Electronics SKU: PRT-00778
L1 L2 = wuerth-elektronik:WE-CBF: SMD EMI Suppression Ferrite Beads
LED1-LED8 = led:LED: LED
P1 = SparkFun:PTC: Resettable Fuse PTC
R1-R3 R6-R35 R38-R63 R66-R96 R99-R117 = rcl:R-US_: RESISTOR, American symbol
R4 R5 R36 R37 R64 R65 R97 R98 = pot-alps:POT_US

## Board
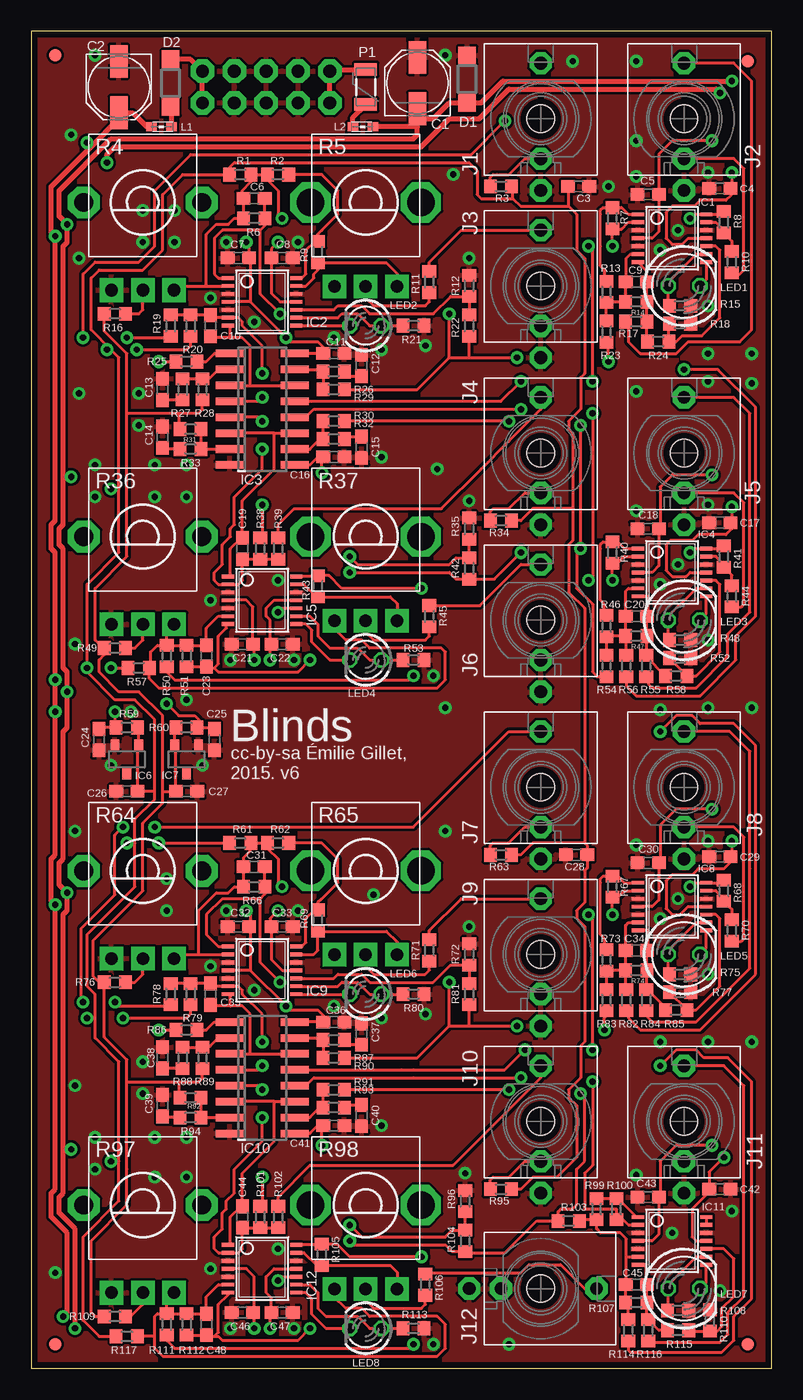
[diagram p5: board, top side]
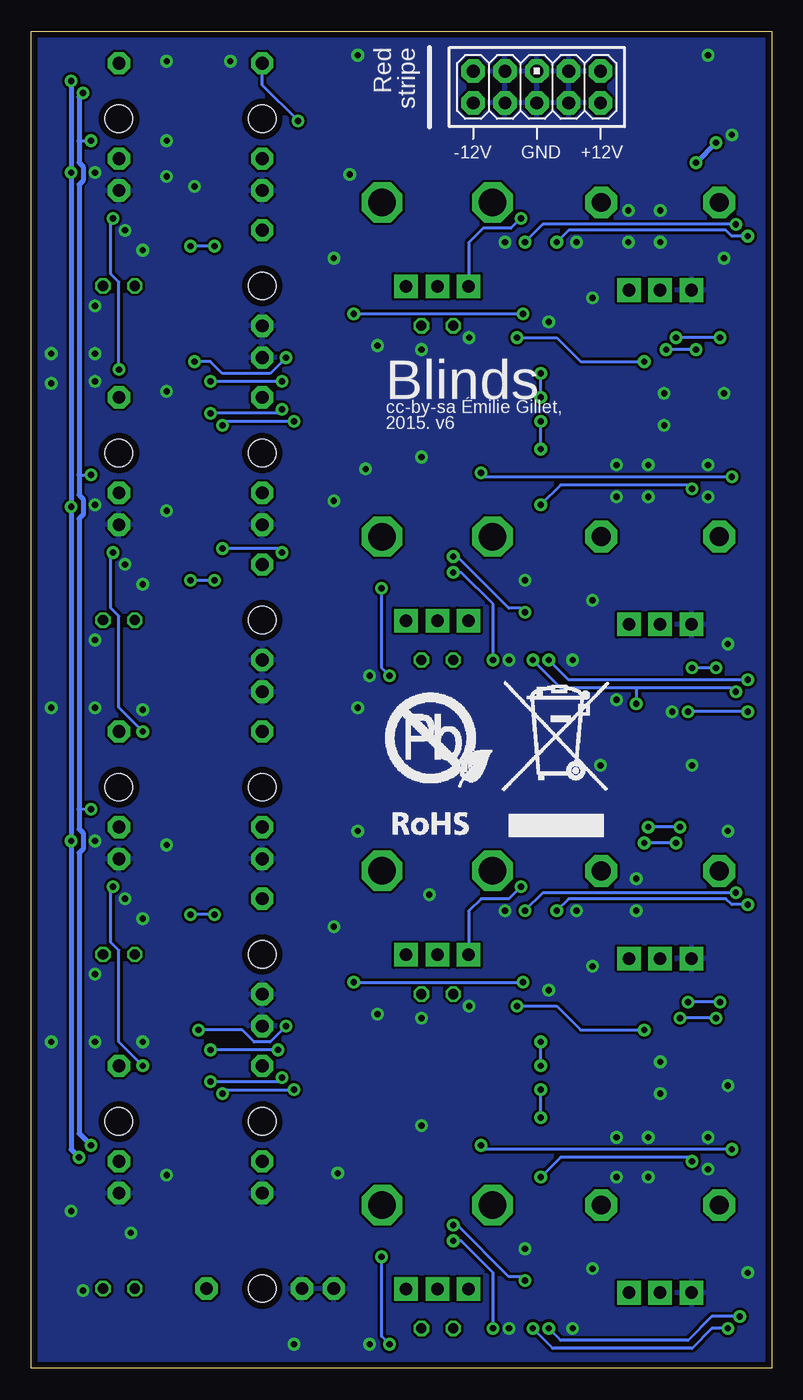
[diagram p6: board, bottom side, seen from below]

Size 59.05 x 106.68 mm. Coordinates in mm from the lower left corner, seen from the top.
Outline: 0,0 59.05,0 59.05,106.68 0,106.68 0,0
Copper layers (1*16): Top 0.035mm / dielectric 1.5mm / Bottom 0.035mm
Design rules "PCBCart-Standard": minimum track width 8mil, minimum drill 0.4mm, track to track 8mil, track to pad 8mil, pad to pad 8mil, via to via 8mil, smd to smd 8mil, copper to edge 20mil, drill to drill 8mil, minimum pad ring 8mil, minimum via ring 10mil, stop-mask expansion 3mil, vias tented up to drill 25mil, thermal gap 8mil

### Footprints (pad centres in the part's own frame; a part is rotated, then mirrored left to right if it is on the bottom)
PANASONIC_C = smd 2.6 x 1.4: + 2.05,0; - -2.05,0
C0603 = smd 1.1 x 1: 1 -0.85,0; 2 0.85,0
SOD123 = smd 1.4 x 1.4: A 1.9,0; C -1.9,0
TSSOP14 = smd 0.305 x 0.991: 1 -1.905,-2.718; 2 -1.27,-2.718; 3 -0.635,-2.718; 4 0,-2.718; 5 0.635,-2.718; 6 1.27,-2.718; 7 1.905,-2.718; 8 1.905,2.718; 9 1.27,2.718; 10 0.635,2.718; 11 0,2.718; 12 -0.635,2.718; 13 -1.27,2.718; 14 -1.905,2.718
SOIC16N = smd 0.6 x 2.2: 1 -4.445,-2.6; 2 -3.175,-2.6; 3 -1.905,-2.6; 4 -0.635,-2.6; 5 0.635,-2.6; 6 1.905,-2.6; 7 3.175,-2.6; 8 4.445,-2.6; 9 4.445,2.6; 10 3.175,2.6; 11 1.905,2.6; 12 0.635,2.6; 13 -0.635,2.6; 14 -1.905,2.6; 15 -3.175,2.6; 16 -4.445,2.6
DBZ_R-PDSO-G3 = smd 0.7 x 1: 1 -0.95,-1.1; 2 0.95,-1.1; 3 0,1.1
WQP_PJ_301M6 = drill 1.016 pad 1.778 octagon: P1 0,-5.715; P2 0,-3.175; P3 0,4.445 | hole 2.2: 0,0
FIDUCIAL-1X2 = smd 1 x 1: 1 0,0
AVR_ICSP = drill 1.016 pad 1.88 octagon: 1 -1.27,5.08; 2 1.27,5.08; 3 -1.27,2.54; 4 1.27,2.54; 5 -1.27,0; 6 1.27,0; 7 -1.27,-2.54; 8 1.27,-2.54; 9 -1.27,-5.08; 10 1.27,-5.08
0603 = smd 0.85 x 0.7: 1 -0.9,0; 2 0.7,0
LED5MM = drill 0.813 octagon: A -1.27,0; K 1.27,0
LED3MM = drill 0.813 octagon: A -1.27,0; K 1.27,0
PTC-1206 = smd 1 x 1.8: 1 -1.4,0; 2 1.4,0
R0603 = smd 1 x 1.1: 1 -0.85,0; 2 0.85,0
ALPS_POT_VERTICAL_PS = drill 1 pad 1.88 square: P$1 -2.5,7; P$2 0,7; P$3 2.5,7 | drill 1.5 pad 2.54 octagon: P$4 -4.7,0; P$5 4.7,0
ALPS_POT_VERTICAL = drill 1 pad 1.88 square: P$1 -2.5,6.7; P$2 0,6.7; P$3 2.5,6.7 | drill 2.2 pad 3.175 octagon: P$4 -4.4,0; P$5 4.4,0

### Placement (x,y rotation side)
C1  30.8,102.55 90 top
C2  6.99,102.23 270 top
C3  43.66,94.3 0 top
C4  54.93,94.14 0 top
C5  49.21,93.66 180 top
C6  17.78,93.34 180 top
C7  16.51,88.58 180 top
C8  20,88.58 180 top
C9  48.26,86.68 0 top
C10  14.29,83.19 270 top
C11  24.13,80.96 0 top
C12  26.35,80.01 90 top
C13  10.48,78.11 90 top
C14  10.48,74.3 90 top
C15  26.35,73.5 270 top
C16  24.13,72.71 180 top
C17  54.93,67.47 0 top
C18  49.21,66.99 180 top
C19  16.83,65.41 90 top
C20  48.26,60.01 0 top
C21  16.83,57.78 180 top
C22  20,57.78 180 top
C23  13.97,56.83 90 top
C24  5.4,50.16 270 top
C25  14.61,50.16 270 top
C26  7.62,46.04 180 top
C27  12.38,46.04 0 top
C28  43.5,40.96 180 top
C29  54.93,40.8 0 top
C30  49.21,40.32 180 top
C31  17.78,40.01 180 top
C32  16.51,35.24 180 top
C33  20,35.24 180 top
C34  48.26,33.34 0 top
C35  14.29,29.84 270 top
C36  24.13,27.62 0 top
C37  26.35,26.67 90 top
C38  10.48,24.77 90 top
C39  10.48,20.95 90 top
C40  26.35,20.16 270 top
C41  24.13,19.37 180 top
C42  54.93,14.29 180 top
C43  49.21,13.65 180 top
C44  16.83,12.06 90 top
C45  48.26,6.67 0 top
C46  16.83,4.45 180 top
C47  20,4.45 180 top
C48  13.97,3.49 90 top
D1  34.77,102.87 270 top
D2  11.11,102.55 90 top
IC1  51.12,90.17 270 top
IC2  18.41,85.09 270 top
IC3  18.41,76.52 270 top
IC4  51.12,63.5 270 top
IC5  18.41,61.28 270 top
IC6  7.62,48.58 180 top
IC7  12.38,48.58 180 top
IC8  51.12,36.83 270 top
IC9  18.41,31.75 270 top
IC10  18.41,23.18 270 top
IC11  51.12,10.16 270 top
IC12  18.41,7.94 270 top
J1  40.64,99.69 0 top
J2  52.07,99.69 0 top
J3  40.64,86.36 0 top
J4  40.64,73.03 0 top
J5  52.07,73.03 0 top
J6  40.64,59.69 0 top
J7  40.64,46.35 0 top
J8  52.07,46.35 0 top
J9  40.64,33.02 0 top
J10  40.64,19.68 0 top
J11  52.07,19.68 0 top
J12  40.64,6.35 270 top
JP1  1.91,104.78 0 top
JP2  57.15,104.3 0 top
JP3  1.91,1.91 0 top
JP4  57.15,1.91 0 top
JP5  18.73,102.23 270 bottom
L1  10.48,99.06 0 top
L2  26.35,99.06 180 top
LED1  52.07,86.36 0 top
LED2  26.67,83.19 180 top
LED3  52.07,59.69 0 top
LED4  26.67,56.52 180 top
LED5  52.07,33.02 0 top
LED6  26.67,29.84 180 top
LED7  52.07,6.35 0 top
LED8  26.67,3.17 180 top
P1  26.67,102.23 90 top
R1  16.67,95.25 180 top
R2  19.68,95.25 0 top
R3  37.47,94.3 180 top
R4  8.89,93.03 180 top
R5  26.67,93.03 180 top
R6  17.78,91.76 180 top
R7  46.35,91.76 270 top
R8  55.24,91.44 270 top
R9  22.86,89.06 270 top
R10  55.88,88.27 270 top
R11  31.75,86.68 90 top
R12  34.92,86.36 90 top
R13  45.88,85.88 90 top
R14  48.26,85.09 180 top
R15  51.75,84.77 0 top
R16  6.67,84.14 180 top
R17  48.26,83.5 0 top
R18  51.75,83.34 0 top
R19  11.11,83.19 270 top
R20  12.7,83.19 270 top
R21  30.48,83.19 0 top
R22  34.92,83.19 270 top
R23  45.88,82.71 270 top
R24  50.01,81.91 180 top
R25  12.38,80.33 0 top
R26  24.13,79.53 180 top
R27  12.06,78.11 90 top
R28  13.65,78.11 270 top
R29  24.13,78.11 0 top
R30  24.13,75.56 0 top
R31  12.7,74.93 180 top
R32  24.13,74.14 180 top
R33  12.7,73.34 0 top
R34  37.47,67.63 180 top
R35  34.92,66.99 90 top
R36  8.89,66.36 180 top
R37  26.67,66.36 180 top
R38  18.26,65.41 90 top
R39  19.68,65.41 90 top
R40  46.35,65.09 270 top
R41  55.24,64.77 270 top
R42  34.92,63.82 270 top
R43  22.86,62.39 270 top
R44  55.88,61.59 270 top
R45  31.75,60.01 90 top
R46  45.88,59.21 90 top
R47  48.26,58.42 180 top
R48  51.75,58.1 0 top
R49  6.67,57.47 180 top
R50  10.79,56.83 270 top
R51  12.38,56.83 90 top
R52  51.75,56.67 0 top
R53  30.48,56.52 0 top
R54  45.88,56.04 270 top
R55  49.05,56.04 90 top
R56  47.47,56.04 270 top
R57  8.57,55.88 180 top
R58  51.43,55.24 180 top
R59  7.62,51.12 0 top
R60  12.38,51.12 180 top
R61  16.67,41.91 180 top
R62  19.68,41.91 0 top
R63  37.47,40.96 180 top
R64  8.89,39.69 180 top
R65  26.67,39.69 180 top
R66  17.78,38.42 180 top
R67  46.35,38.42 270 top
R68  55.24,38.1 270 top
R69  22.86,35.72 270 top
R70  55.88,34.92 270 top
R71  31.75,33.34 90 top
R72  34.92,33.02 90 top
R73  45.88,32.54 90 top
R74  48.26,31.75 180 top
R75  51.75,31.43 0 top
R76  6.67,30.8 180 top
R77  51.75,30 0 top
R78  11.11,29.84 270 top
R79  12.7,29.84 270 top
R80  30.48,29.84 0 top
R81  34.92,29.84 270 top
R82  47.47,29.37 270 top
R83  45.88,29.37 270 top
R84  49.05,29.37 90 top
R85  51.44,28.57 180 top
R86  12.38,26.99 0 top
R87  24.13,26.19 180 top
R88  12.06,24.77 90 top
R89  13.65,24.77 270 top
R90  24.13,24.77 0 top
R91  24.13,22.23 0 top
R92  12.7,21.59 180 top
R93  24.13,20.8 180 top
R94  12.7,20 0 top
R95  37.47,14.29 180 top
R96  34.61,13.34 90 top
R97  8.89,13.02 180 top
R98  26.67,13.02 180 top
R99  45.09,12.7 90 top
R100  46.67,12.7 270 top
R101  18.26,12.06 90 top
R102  19.68,12.06 90 top
R103  42.86,11.75 180 top
R104  34.61,10.16 270 top
R105  23.18,9.05 270 top
R106  31.43,6.67 90 top
R107  48.26,5.24 180 top
R108  51.59,4.6 0 top
R109  6.67,4.13 180 top
R110  54.13,3.81 90 top
R111  10.79,3.49 270 top
R112  12.38,3.49 90 top
R113  30.48,3.17 0 top
R114  47.63,3.02 270 top
R115  51.59,3.02 180 top
R116  49.21,3.02 90 top
R117  7.62,2.54 180 top
U$2  [ROHS_BIG]  32.07,41.59 0 bottom

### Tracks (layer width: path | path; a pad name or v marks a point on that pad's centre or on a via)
1_TO_2  (via drill 0.5)
  Top 0.254: R8.1 55.03,92.08 IC1.14 52.86,92.08 v52.55,91.76 | v52.07,79.69 54.77,79.69 57.78,76.68 57.78,60.01 56.2,58.42 56.2,56.52 53.34,53.66 48.26,53.66 47.47,54.45 R56.2
  Bottom 0.254: v52.55,91.76 52.7,91.6 52.7,87.31 52.07,86.68 v52.07,79.69 | v52.55,91.76
2_TO_3  (via drill 0.5)
  Top 0.254: R41.1 55.03,65.41 IC4.14 52.86,65.41 v52.55,65.09 | v50.16,50.8 51.44,52.07 52.7,52.07 53.34,51.44 56.04,51.44 57.78,49.69 57.78,31.43 53.34,26.99 48.58,26.99 47.62,27.94 47.62,28.36 R82.2
  Bottom 0.254: v50.16,50.8 52.07,52.7 52.07,60.01 52.7,60.64 52.7,64.93 v52.55,65.09
3_TO_4  (via drill 0.5)
  Top 0.254: R68.1 55.03,38.73 IC8.14 52.86,38.73 v52.55,38.42 | R114.2 47.62,1.43 47.78,1.27 55.09,1.27 56.04,2.22 56.04,4.13 57.47,5.56 57.47,22.86 55.56,24.77 53.66,24.77 53.02,25.4 51.44,25.4 v50.16,24.13
  Bottom 0.254: v52.55,38.42 52.7,38.26 52.7,33.97 52.07,33.34 52.07,26.04 v50.16,24.13
AREF_+5
  Top 0.254: IC11.14 IC11.13
AREF_+10  (via drill 0.5)
  Top 0.254: R20.2 12.7,81.6 12.38,81.28 v8.41,81.28 | 6.99,70.17 6.99,65.09 4.45,62.55 v4.45,55.88 4.45,55.56 6.67,53.34 8.26,53.34 9.84,51.75 9.84,46.04 | 6.99,70.17 6.99,80.64 6.35,81.28 | 6.35,81.28 4.76,82.87 4.76,87 5.4,87.63 8.89,87.63 10.48,89.22 10.48,93.66 12.06,95.25 R1.2 15.88,95.31 15.88,95.89 16.19,96.2 34.92,96.2 35.56,95.57 35.56,93.66 35.88,93.34 38.42,93.34 | 6.35,81.28 v6.03,81.28 | 9.84,46.04 C26.1 8.47,49.58 IC6.1 8.57,51.02 R59.2 | v6.35,55.88 R57.2 | 8.26,41.91 8.26,38.42 4.45,34.61 4.45,30.48 5.08,29.84 5.08,27.94 | 8.26,41.91 8.26,43.81 9.84,45.4 9.84,46.04 | R79.2 12.7,28.26 12.38,27.94 v7.3,27.94 | v10.16,41.91 R61.2 | 8.26,41.91 v7.62,41.91 | R117.2 5.4,2.54 4.13,3.81 4.13,10.48 6.99,13.34 6.99,16.51 | 6.99,16.51 6.99,24.45 5.08,26.35 5.08,27.94 | R101.2 18.41,13.07 v18.41,15.24 | 6.99,16.51 v6.35,16.51 | R38.2 18.41,66.41 v18.41,68.9 | 6.99,70.17 v6.35,70.17 | 5.08,27.94 v4.45,27.94 | 43.18,68.58 43.18,66.04 42.86,65.72 42.86,61.91 44.13,60.64 44.13,41.91 | 43.18,68.58 43.18,74.61 42.86,74.93 42.86,75.56 43.81,76.52 43.81,79.06 44.13,79.38 44.13,88.58 43.5,89.22 43.5,92.08 42.86,92.71 | R95.1 39.05,14.29 40.01,15.24 41.91,15.24 43.5,16.83 43.5,20.95 42.86,21.59 42.86,22.23 43.81,23.18 43.81,25.72 44.13,26.04 44.13,35.24 43.5,35.88 43.5,36.51 44.13,37.15 44.13,39.69 44.35,39.9 C28.1 44.35,41.7 44.13,41.91 | R63.1 39.05,40.96 40.01,41.91 44.13,41.91 | R34.1 39.05,67.63 40.01,68.58 43.18,68.58 | 38.42,93.34 39.05,92.71 42.86,92.71 | R3.1 38.42,94.19 38.42,93.34 | C3.1 42.86,94.24 42.86,92.71
  Bottom 0.254: v6.03,81.28 v8.41,81.28 | v4.45,55.88 v6.35,55.88 | v7.62,41.91 v10.16,41.91 | v18.41,15.24 16.83,16.83 6.67,16.83 v6.35,16.51 | v18.41,68.9 16.83,70.48 6.67,70.48 v6.35,70.17 | v4.45,27.94 v7.3,27.94
AREF_-10
  Top 0.254: 7.62,76.2 7.62,64.77 5.08,62.23 5.08,58.1 5.71,57.47 R49.2 5.82,56.94 5.4,56.52 5.4,55.56 6.99,53.98 8.57,53.98 10.48,52.07 10.48,46.04 | 7.62,76.2 7.62,80.96 5.82,82.77 R16.2 | 10.48,46.04 C27.1 11.53,49.58 IC7.2 11.43,51.02 R60.2 | 10.48,46.04 10.48,45.09 8.89,43.5 8.89,38.1 4.92,34.13 4.92,31.27 5.4,30.8 R76.2 5.82,26.41 7.62,24.61 7.62,22.86 | R92.2 11.75,21.69 11.75,22.86 | 7.62,22.86 7.62,15.88 7.62,13.02 4.76,10.16 4.76,4.45 5.08,4.13 R109.2 | 7.62,22.86 11.75,22.86 | R89.2 13.65,23.18 13.34,22.86 11.75,22.86 | R31.2 11.75,75.03 11.75,76.2 | 7.62,76.2 11.75,76.2 | R28.2 13.65,76.52 13.34,76.2 11.75,76.2
CV_IN_1
  Top 0.254: J3.P3 34.29,90.81 31.75,88.27 R11.2
FOO
  Top 0.254: R27.2 R28.1 13.76,79.06 14.29,79.06 14.92,79.69 IC3.2
FOO1
  Top 0.254: IC3.7 R33.2 R31.1
FOO2
  Top 0.254: IC10.2 14.92,26.35 14.29,25.72 13.76,25.72 R89.1 R88.2
FOO3
  Top 0.254: R92.1 R94.2 IC10.7
GAIN_1  (via drill 0.5)
  Top 0.254: IC2.1 14.92,87 14.61,87.31 14.61,90.17 15.24,90.81 18.26,90.81 | v19.84,84.14 18.26,85.72 18.26,90.81 | 18.26,90.81 18.63,91.18 R6.1 C6.1 | R29.2 30.8,78.11 33.34,80.64 | R23.2 46.04,81.7 v46.04,80.33 | 33.34,80.64 34.92,80.64 | 34.92,80.64 v38.73,80.64 | 33.34,80.64 v33.34,84.14 | 34.92,80.64 R22.2
  Bottom 0.254: v46.04,80.33 44.77,80.33 43.81,79.38 40.01,79.38 v38.73,80.64 | v33.34,84.14 v19.84,84.14
GAIN_2  (via drill 0.5)
  Top 0.254: 14.61,55.88 14.07,55.88 14.07,55.98 C23.1 R51.1 | 14.61,55.88 14.92,55.56 21.27,55.56 v22.23,56.52 | 14.61,55.88 14.92,56.2 14.92,58.42 15.56,59.05 15.56,59.37 IC5.7 | 46.09,55.19 R54.2 45.14,55.19 44.77,55.56 44.77,60.96 43.5,62.23 43.5,65.09 v43.81,65.41 v43.81,75.25 | v38.1,75.56 R30.2 | v25.4,63.5 33.34,63.5 33.87,62.97 R42.2 36.93,62.97 v39.05,65.09
  Bottom 0.254: v25.4,63.5 24.77,63.5 22.23,60.96 v22.23,56.52 | v39.05,65.09 39.37,65.41 v43.81,65.41 | v38.1,75.56 43.5,75.56 v43.81,75.25
GAIN_3  (via drill 0.5)
  Top 0.254: C31.1 R66.1 18.63,37.84 18.26,37.47 | IC9.1 14.92,33.66 13.97,34.61 13.97,36.2 15.24,37.47 18.26,37.47 | 45.82,28.57 R83.2 45.88,28.1 45.72,27.94 v45.72,26.99 | 33.34,27.3 34.92,27.3 | 34.92,27.3 v38.73,27.3 | 18.26,37.47 18.26,32.38 v19.84,30.8 | 33.34,27.3 v33.34,30.8 | 33.34,27.3 30.8,24.77 R90.2 | 34.92,27.3 R81.2
  Bottom 0.254: v38.73,27.3 40.01,26.04 41.27,26.04 42.23,26.99 v45.72,26.99 | v33.34,30.8 v19.84,30.8
GAIN_4  (via drill 0.5)
  Top 0.254: R112.1 C48.1 14.07,2.54 14.61,2.54 | 14.61,2.54 14.92,2.86 14.92,5.08 15.7,5.86 IC12.7 | 14.61,2.54 14.92,2.54 15.24,2.22 21.27,2.22 v22.23,3.17 | v38.1,22.23 R91.2 | v43.81,21.91 44.13,21.59 44.13,16.51 43.5,15.88 43.5,13.02 43.18,12.7 42.23,12.7 42.01,12.48 R103.2 40.32,11.75 37.78,9.21 34.71,9.21 R104.2 33.55,9.31 33.02,9.84 25.72,9.84 v25.4,10.16
  Bottom 0.254: v22.23,3.17 22.23,7.62 24.77,10.16 v25.4,10.16 | v38.1,22.23 43.5,22.23 v43.81,21.91
GND  (via drill 0.5)
  other vias: 51.59,90.8 50.16,89.22 53.98,84.77 21.27,89.85 53.98,95.41 48.26,95.09 15.56,89.85 27.94,81.28 14.29,85.41 27.94,72.71 32.07,55.24 15.88,56.52 20.95,56.52 53.98,58.1 53.98,68.9 51.59,64.13 50.17,62.55 48.26,68.42 8.57,77.79 8.57,75.25 19.68,62.87 14.29,61.28 57.47,78.58 24.13,82.23 12.38,72.07 17.78,83.5 12.38,69.53 8.89,92.39 8.89,89.85 11.43,92.39 11.43,89.85 5.08,72.07 5.08,69.53 3.49,57.78 7.94,52.39 13.65,48.1 6.35,48.1 12.38,53.34 9.84,72.07 9.84,69.53 31.43,81.6 34.92,69.21 33.02,104.78 5.08,104.78 10.79,39.05 10.79,36.51 8.89,24.45 8.89,21.91 9.84,18.41 12.38,18.41 9.84,15.24 12.38,15.24 14.29,32.07 17.78,30.16 15.56,36.51 21.27,36.51 24.13,28.89 27.94,27.94 27.94,19.37 31.43,28.26 14.29,7.94 19.68,9.53 15.88,3.17 20.95,3.17 32.07,1.91 34.61,15.56 48.26,41.75 53.98,42.07 51.59,37.47 50.16,35.88 53.98,31.43 57.47,26.04 55.88,12.54 51.12,10.79 53.98,80.96 57.47,80.96 57.47,52.7 53.98,52.7 50.16,26.04 53.98,26.04 54.93,6.19 48.26,15.4 33.66,95.25 1.91,7.62 3.49,22.54 3.49,42.86 3.81,77.79 3.81,88.58 3.17,98.42 48.26,104.3 43.18,104.3 38.1,1.91 33.02,42.86 27.3,37.78 33.02,52.7 32.38,71.75 34.92,88.58 48.26,97.95 48.26,77.95 50.16,52.55 5.08,18.41 5.08,15.88 53.98,78.74 34.92,35.24 46.04,94.3
  pour Bottom: 0,106.68 0,0 59.05,0 59.05,106.68
  pour Top (isolate 0.203): 0,106.68 0,0 59.05,0 59.05,106.68
N$1
  Top 0.254: R25.2 13.97,80.33 14.61,80.96 IC3.1
N$2
  Top 0.254: R16.1 8.57,84.14 8.89,84.45 R4.P$2
N$3  (via drill 0.5)
  Top 0.254: IC3.13 28.89,77.15 | 28.89,77.15 30.48,77.15 | R7.2 46.14,91.12 R7.2 | IC1.2 | IC1.2 47.62,91.44 47.09,90.91 R7.2 | v46.35,89.53 R7.2 | v44.45,89.53 44.77,89.22 44.77,82.23 v44.77,78.74 | v39.05,78.74 37.47,77.15 28.89,77.15
  Bottom 0.254: v44.45,89.53 v46.35,89.53 | v39.05,78.74 v44.77,78.74
N$4
  Top 0.254: IC2.8 LED2.K
N$5
  Top 0.254: R5.P$1 29.17,87.35 28.31,88.21 R9.2 22.86,87.63 22.54,87.31 22.54,87 21.91,86.36 IC2.13
N$6
  Top 0.254: J5.P3 56.04,77.47 57.31,76.2 57.31,60.33 55.56,58.58 55.56,56.83 53.02,54.29 49.53,54.29 49.21,54.61 49.21,55.03 R55.1
N$7
  Top 0.254: J2.P3 56.04,104.14 57.47,102.71 57.47,82.87 56.52,81.92 52.39,81.92 51.44,80.96 48.58,80.96 47.62,81.92 47.62,83.29 R17.1
N$8
  Top 0.254: R2.2 23.18,95.25 24.45,93.98 24.45,92.08 23.18,90.81 22.86,90.49 R9.1 22.6,89.91 21.91,89.22 21.91,87.31 21.59,87 IC2.14
N$9  (via drill 0.5)
  Top 0.254: v20,91.76 19.68,92.08 19.68,93.98 18.84,94.83 R2.1 R1.1 17.52,94.67 16.83,93.98 16.83,93.45 C6.2 R6.2 16.19,91.76 15.72,91.28 14.76,91.28 13.97,90.49 13.97,86.36 | R4.P$1 11.72,86.36 13.97,86.36 | 13.97,86.36 IC2.2
  Bottom 0.254: v20,91.76 20.8,90.96 23.02,90.96 24.17,89.81 R5.P$3
N$10
  Top 0.254: IC1.6 | IC1.6 47.78,88.9 47.47,88.58 47.47,86.73 C9.1 47.35,86.62 47.41,86.56 R14.2 45.94,85.09 R13.1 R23.1 | R23.1
N$11
  Top 0.406: JP5.2 JP5.1 12.71,104.45 D2.A
N$12
  Top 0.406: JP5.10 JP5.9 23.94,103.64 P1.2
N$13
  Top 0.406: P1.1 25.65,99.82 L2.2
N$14
  Top 0.254: R5.P$2 26.67,85.41 27.3,84.77 31.43,84.77 31.75,85.09 R11.1
N$15
  Top 0.254: IC2.9 24.45,83.82 24.77,84.14 26.04,84.14 26.99,83.19 LED2.A R21.1
N$16
  Top 0.406: D2.C 11.18,100.59 L1.2
N$17
  Top 0.254: R32.1 25.2,74.35 C15.1
N$18
  Top 0.254: LED1.K 53.84,86.86 IC1.8
N$19
  Top 0.254: IC1.9 53.02,88.9 50.8,86.68 LED1.A 50.8,84.88 R15.1
N$20
  Top 0.254: R27.1 C13.1
N$21  (via drill 0.5)
  Top 0.254: R19.2 11.01,82.23 v7.62,82.23 | v4.13,82.23 4.13,87.31 5.08,88.27 8.57,88.27 9.84,89.53 9.84,93.98 12.7,96.84 35.08,96.84 v37.78,99.54
  Bottom 0.254: v37.78,99.54 40.64,102.39 J1.P3 | v4.13,82.23 v7.62,82.23
N$22
  Top 0.254: IC1.13 54.61,91.44 55.24,90.81 R8.2 55.88,89.95 R10.1
N$23
  Top 0.254: 57.31,39.85 57.31,31.91 53.02,27.62 49.53,27.62 49.21,27.94 49.21,28.36 R84.1 | J8.P3 55.72,50.8 57.31,49.21 57.31,39.85 | 57.31,39.85
N$24
  Top 0.254: R30.1 R32.2 23.02,74.14 22.23,73.34 IC3.10
N$25
  Top 0.254: J2.P2 56.04,96.52 56.83,95.73 56.83,87.63 56.52,87.31 55.98,87.31 R10.2
N$26  (via drill 0.5)
  Top 0.254: IC3.12 21.91,75.88 22.54,76.52 30.16,76.52 v39.05,76.52 | IC4.2 | IC4.2 47.31,64.77 46.77,64.24 R40.2 v46.35,62.87 | v44.77,76.2 44.77,63.18 v44.45,62.87
  Bottom 0.254: v44.45,62.87 v46.35,62.87 | v39.05,76.52 39.37,76.2 v44.77,76.2
N$27
  Top 0.254: R47.2 C20.1 47.41,62.02 47.62,62.23 IC4.6 | 47.35,56.89 47.41,56.95 R56.1 47.47,58.36 R47.2 | R47.2 45.94,58.42 R46.1 R54.1
N$28
  Top 0.254: J6.P3 39.05,64.14 35.77,60.86 R45.2
N$29
  Top 0.254: R37.P$1 29.17,61 28.63,61.54 R43.2 22.76,61.54 21.75,62.55 IC5.13
N$30  (via drill 0.5)
  Top 0.254: v31.11,62.23 24.77,62.23 23.76,63.24 R43.1 22.8,63.18 IC5.14 | R50.2 10.79,55.56 11.43,54.93 30.16,54.93 v30.48,55.24
  Bottom 0.254: v30.48,55.24 31.11,55.88 v31.11,62.23
N$31
  Top 0.254: R51.2 C23.2 13.97,59.05 14.92,60.01 IC5.6 | R50.1 R51.2 | R51.2 12.34,57.72 | R50.1 10.06,57.68 9.53,57.15 9.53,55.98 R57.1 9.42,55.03 10.16,54.29 32.38,54.29 33.02,54.93 33.02,57.15 32.7,57.47 26.99,57.47 26.35,58.1 25.08,58.1 24.17,59.02 R37.P$3 | R36.P$1 10.79,58.76 R50.1
N$32
  Top 0.254: R36.P$2 8.89,58.1 8.26,57.47 R49.1
N$33
  Top 0.254: IC5.8 21.91,59.37 22.38,58.9 22.38,57.94 23.81,56.52 LED4.K
N$34
  Top 0.254: R53.1 LED4.A 26.99,56.52 26.04,57.47 23.81,57.47 22.86,58.42 22.86,59.37 22.23,60.01 IC5.9
N$35
  Top 0.254: LED3.K 53.84,60.19 IC4.8
N$36
  Top 0.254: IC4.9 53.02,62.23 50.8,60.01 LED3.A 50.8,58.2 R48.1
N$37
  Top 0.254: IC4.13 54.61,64.77 55.24,64.14 R41.2 55.88,63.28 R44.1
N$38
  Top 0.254: J5.P2 56.04,69.85 56.83,69.06 56.83,60.96 56.62,60.74 R44.2
N$39
  Top 0.254: IC4.1 47.31,65.41 46.77,65.94 R40.1 45.62,65.94 45.4,65.72 45.4,65.41 45.4,61.28 45.72,60.96 45.72,60.22 R46.2
N$40
  Top 0.254: R37.P$2 26.67,58.74 27.3,58.1 31.43,58.1 31.75,58.42 R45.1
N$41
  Top 0.254: C14.1 10.58,73.34 R33.1
N$42  (via drill 0.5)
  Top 0.254: R39.1 R38.1 C19.1 16.83,62.87 16.51,62.55 IC5.2 14.92,62.55 14.61,62.87 14.61,63.5 15.24,64.14 15.24,65.72 15.88,66.36 15.88,66.99 16.19,67.31 16.19,69.53 18.41,71.75 v18.41,73.34 | v18.41,75.56 18.1,75.88 IC3.5
  Bottom 0.254: v18.41,73.34 v18.41,75.56
N$43
  Top 0.254: 19.37,74.61 IC3.6 | 19.37,74.61 IC3.11 | IC5.1 15.88,63.36 15.88,65.41 16.73,66.25 C19.2 | C19.2 16.73,66.36 16.83,66.46 | 19.37,74.61 19.37,71.75 16.83,69.22 C19.2
N$44
  Top 0.254: R39.2 19.68,67.31 20.95,68.58 32.7,68.58 35.88,71.75 38.1,73.98 40.64,76.52 J4.P3
N$45
  Top 0.254: R87.1 25.35,25.82 C37.1
N$46
  Top 0.254: IC10.15 23.12,26.35 R87.2 R90.1
N$47
  Top 0.254: R26.1 25.35,79.16 C12.1
N$48  (via drill 0.5)
  Top 0.254: IC10.13 29.53,23.81 | 29.53,23.81 30.48,23.81 | IC8.2 47.31,38.1 46.77,37.57 R67.2 46.25,37.57 46.04,37.78 46.35,37.47 v46.35,36.2 | v44.45,36.2 44.77,35.88 v44.77,25.4 | v39.37,25.4 37.78,23.81 29.53,23.81
  Bottom 0.254: v44.45,36.2 v46.35,36.2 | v39.37,25.4 v44.77,25.4
N$49
  Top 0.254: IC8.6 47.62,35.56 47.41,35.34 C34.1 R74.2 | R82.1 47.41,30.27 R74.2 | R74.2 45.94,31.75 R73.1 R83.1 | R83.1
N$50
  Top 0.254: R71.2 31.75,34.92 34.29,37.47 J9.P3
N$51
  Top 0.254: IC9.13 22.54,33.02 22.86,33.34 R69.2 28.31,34.87 29.17,34.01 R65.P$1
N$52
  Top 0.254: R62.2 23.18,41.91 24.45,40.64 24.45,38.73 23.18,37.47 22.86,37.15 R69.1 22.6,36.57 21.91,35.88 21.91,33.97 21.59,33.66 IC9.14
N$53  (via drill 0.5)
  Top 0.254: v20,38.42 19.68,38.73 19.68,40.64 18.84,41.49 R62.1 R61.1 17.46,41.85 17.46,41.27 16.93,40.74 C31.2 R66.2 16.19,38.42 15.72,37.94 14.76,37.94 13.34,36.51 13.34,33.02 | R64.P$1 11.72,33.02 13.34,33.02 | 13.34,33.02 IC9.2
  Bottom 0.254: v20,38.42 20.95,37.47 23.18,37.47 24.17,36.47 R65.P$3
N$54
  Top 0.254: R3.2 36.62,95.03 36.83,95.25 37.15,95.25 38.1,95.25 39.37,96.52 J1.P2
N$55
  Top 0.254: R76.1 8.26,30.8 8.89,31.43 R64.P$2
N$56
  Top 0.254: IC9.8 LED6.K
N$57
  Top 0.254: IC9.9 24.45,30.48 24.77,30.8 26.04,30.8 26.99,29.84 LED6.A R80.1
N$58
  Top 0.254: LED5.K 53.84,33.52 IC8.8
N$59
  Top 0.254: IC8.9 53.02,35.56 50.8,33.34 LED5.A 50.8,31.54 R75.1
N$60
  Top 0.254: IC8.13 54.61,38.1 55.24,37.47 R68.2 55.88,36.62 R70.1
N$61
  Top 0.254: J8.P2 56.04,43.18 56.83,42.39 56.83,34.29 56.62,34.08 R70.2
N$62
  Top 0.254: IC8.1 47.31,38.73 46.77,39.27 R67.1 45.62,39.27 45.4,39.05 45.4,38.73 45.4,34.61 45.72,34.29 45.72,33.55 R73.2
N$63
  Top 0.254: R88.1 C38.1
N$64
  Top 0.254: IC1.1 | IC1.1 47.62,92.08 47.09,92.61 R7.1 45.62,92.61 45.4,92.39 45.4,92.08 45.4,89.53 45.4,87.95 45.72,87.63 45.72,87.31 45.72,86.89 R13.2
N$65  (via drill 0.5)
  Top 0.254: v18.41,77.47 18.1,77.15 IC3.4 | R19.1 R20.1 C10.1 14.5,83.82 IC2.6 16.51,83.82 16.83,83.5 16.83,83.19 18.41,81.6 v18.41,79.38
  Bottom 0.254: v18.41,77.47 v18.41,79.38
N$66
  Top 0.254: IC3.3 17.46,78.42 | 17.46,78.42 IC3.14 | C10.2 14.39,82.23 15.88,82.23 | 15.88,82.23 16.83,82.23 17.46,81.6 17.46,78.42 | IC2.7 15.88,83.01 15.88,82.23
N$67  (via drill 0.5)
  Top 0.254: R78.1 R79.1 C35.1 14.5,30.48 IC9.6 16.51,30.48 16.83,30.16 16.83,29.84 18.41,28.26 v18.41,26.04 | IC10.4 18.1,23.81 v18.41,24.13
  Bottom 0.254: v18.41,24.13 v18.41,26.04
N$68
  Top 0.254: C35.2 14.39,28.89 15.88,28.89 | 15.88,28.89 16.83,28.89 17.46,28.26 17.46,25.08 | IC10.3 17.46,25.08 | 17.46,25.08 IC10.14 | IC9.7 15.88,29.67 15.88,28.89
N$69
  Top 0.254: R102.2 19.68,13.65 22.23,16.19 33.66,16.19 40.64,23.18 J10.P3 40.64,23.5
N$70
  Top 0.254: R65.P$2 26.67,32.07 27.3,31.43 31.43,31.43 31.75,31.75 R71.1
N$71
  Top 0.254: J11.P3 55.24,24.13 56.83,22.54 56.83,5.71 55.56,4.45 55.56,2.7 54.93,2.06 49.31,2.06 R116.1
N$72
  Top 0.254: R93.1 25.2,21.01 C40.1
N$73
  Top 0.254: R91.1 R93.2 23.02,20.8 22.23,20 IC10.10
N$74  (via drill 0.5)
  Top 0.254: IC10.12 21.91,22.54 22.54,23.18 30.48,23.18 v39.05,23.18 | IC11.2 47.62,11.43 47.2,11.85 R100.2 46.67,12.7 44.13,12.7 44.13,15.56 44.77,16.19 v44.77,22.86
  Bottom 0.254: v39.05,23.18 39.37,22.86 v44.77,22.86
N$75
  Top 0.254: IC3.15 23.12,79.69 R26.2 R29.1
N$76
  Top 0.254: R114.1 47.62,5.02 R107.2 C45.1 47.47,6.72 47.47,8.89 | 47.47,8.89 47.47,10.32 46.99,10.79 45.4,10.79 45.09,11.11 R99.1 43.81,11.85 R103.1 | 47.47,8.89 IC11.6
N$77
  Top 0.254: R106.2 31.54,7.62 39.05,7.62 39.69,8.26 42.23,8.26 44.13,6.35 J12.P3
N$78
  Top 0.254: R98.P$1 29.17,7.66 28.63,8.2 R105.2 22.76,8.2 21.75,9.21 IC12.13
N$79  (via drill 0.5)
  Top 0.254: R111.2 10.79,2.22 11.43,1.59 30.16,1.59 v30.48,1.91 | v31.11,8.89 25.4,8.89 24.39,9.9 R105.1 23.12,9.84 IC12.14
  Bottom 0.254: v30.48,1.91 31.11,2.54 v31.11,8.89
N$80
  Top 0.254: R111.1 10.06,4.34 9.84,4.13 9.84,2.54 | R111.1 R112.2 | R112.2 C48.2 13.97,5.71 14.92,6.67 IC12.6 | R112.2 12.34,4.38 | R98.P$3 24.17,5.67 25.08,4.76 26.35,4.76 26.99,4.13 32.38,4.13 33.02,3.49 33.02,1.59 32.38,0.95 10.48,0.95 9.84,1.59 9.84,2.54 | 9.84,2.54 R117.1 | R97.P$1 10.79,5.42 R111.1
N$81
  Top 0.254: R109.1 7.94,4.13 8.89,5.08 R97.P$2
N$82
  Top 0.254: IC12.8 21.91,6.03 22.38,5.56 22.38,4.29 23.5,3.17 LED8.K
N$83
  Top 0.254: IC12.9 22.23,6.67 22.86,6.03 22.86,4.76 23.5,4.13 26.04,4.13 26.99,3.17 LED8.A R113.1
N$84
  Top 0.254: LED7.K 53.84,6.84 IC11.8
N$85
  Top 0.254: IC11.9 53.02,8.89 50.8,6.67 LED7.A 50.8,4.66 R108.1
N$86
  Top 0.254: R86.2 13.97,26.99 14.61,27.62 IC10.1
N$87
  Top 0.254: J4.P2 39.37,69.85 38.1,68.58 36.83,68.58 36.62,68.36 R34.2
N$88
  Top 0.254: R99.2 R100.1 46.89,13.34 46.99,13.34 48.26,12.06 IC11.1
N$89
  Top 0.254: R98.P$2 26.67,5.4 27.3,4.76 31.11,4.76 31.43,5.08 R106.1
N$90
  Top 0.254: C39.1 10.58,20 R94.1
N$91  (via drill 0.5)
  Top 0.254: R102.1 R101.1 C44.1 16.83,9.53 16.51,9.21 IC12.2 14.92,9.21 14.61,9.53 14.61,10.48 15.24,11.11 15.24,12.38 15.56,12.7 15.56,13.34 16.19,13.97 16.19,15.88 18.41,18.1 v18.41,20 | IC10.5 18.1,22.54 v18.41,22.23
  Bottom 0.254: v18.41,20 v18.41,22.23
N$92
  Top 0.254: 19.37,21.27 IC10.6 | 19.37,21.27 IC10.11 | IC12.1 15.88,10.02 15.88,12.06 16.73,12.91 | 16.73,12.91 C44.2 | 16.73,12.91 16.83,13.02 16.83,15.56 19.37,18.1 19.37,21.27
N$93  (via drill 0.5)
  Top 0.254: R78.2 11.01,28.89 6.99,28.89 v6.67,29.21 | v7.3,43.18 6.67,42.55 6.67,37.78 3.97,35.08 3.97,29.69 4.13,29.53 v4.13,29.21 | v9.84,43.18 30.48,43.18 38.1,50.8 J7.P3
  Bottom 0.254: v7.3,43.18 v9.84,43.18 | v4.13,29.21 v6.67,29.21
N$94
  Top 0.254: J7.P2 39.37,43.18 38.1,41.91 36.83,41.91 36.62,41.7 R63.2
N$95
  Top 0.254: J10.P2 39.37,16.51 38.1,15.24 36.83,15.24 36.62,15.03 R95.2
N$96
  Top 0.254: IC1.10 | IC1.10 54.61,89.53 54.93,89.22 54.93,83.82 53.5,82.39 51.91,82.39 51.44,81.92 R24.1 50.86,83.3 R18.1
N$97
  Top 0.254: IC4.10 | IC4.10 54.61,62.87 54.93,62.55 54.93,57.15 53.02,55.24 R58.1 52.28,55.29 R52.1
N$98
  Top 0.254: IC8.10 54.61,36.2 54.93,35.88 54.93,30.48 53.02,28.57 R85.1 52.28,28.62 R77.1
N$99
  Top 0.254: IC2.10 24.13,84.45 24.45,84.77 26.35,84.77 26.99,84.14 32.07,84.14 33.44,85.51 R12.1 R22.1
N$100
  Top 0.254: R115.1 52.5,2.96 R110.1 | R110.1 54.19,3.02 | IC11.10 55.24,9.53 56.04,8.73 56.04,5.71 55.09,4.76 55.09,3.33 54.71,2.96 R110.1
N$101  (via drill 0.5)
  Top 0.254: R96.1 R104.1 33.55,11.01 33.02,10.48 26.35,10.48 v25.4,11.43 | IC12.10 20,7.3 v19.68,6.99
  Bottom 0.254: v19.68,6.99 20,7.3 20.95,7.3 25.08,11.43 v25.4,11.43
N$102
  Top 0.254: R81.1 R72.1 33.44,32.17 32.07,30.8 26.99,30.8 26.35,31.43 24.45,31.43 24.13,31.11 IC9.10
N$103  (via drill 0.5)
  Top 0.254: v25.4,64.77 26.04,64.14 33.34,64.14 33.87,64.67 R42.1 R35.1 | v19.68,60.33 20,60.64 IC5.10
  Bottom 0.254: v25.4,64.77 25.08,64.77 20.95,60.64 20,60.64 v19.68,60.33
OUT1
  Top 0.254: R24.2 49.11,81.96 R17.2 R14.1 C9.2 49.11,87.56 IC1.7
OUT2
  Top 0.254: IC4.7 49.21,61.59 49.21,60.11 C20.2 R47.1 49.11,56.95 R55.2 49.05,56.78 R58.2
OUT3
  Top 0.254: IC8.7 49.21,34.92 49.21,33.44 C34.2 R74.1 49.11,30.27 | 49.11,30.27 R84.2 | 49.11,30.27 50.59,28.8 R85.2
OUT4
  Top 0.254: IC11.7 49.05,8.26 49.05,6.72 C45.2 R107.1 49.11,3.97 R116.2 | R116.2 49.11,3.76 | R116.2 50.06,3.02 R115.2
VCC  (via drill 0.5)
  Top 0.254: v17.14,89.85 17.36,89.64 C7.1 17.46,88.48 17.46,85.09 | v54.29,97.95 51.12,97.95 50.06,96.89 C5.1 50.06,90.7 49.53,90.17 IC1.4 | IC5.4 17.14,61.28 17.68,60.74 C21.1 17.78,57.68 v17.78,56.52 | IC4.4 49.53,63.5 50.06,64.03 C18.1 50.16,67.09 50.16,70.33 51.12,71.28 v54.29,71.28 | IC3.16 C11.1 23.28,81.5 22.86,81.92 20.64,81.92 v20.32,82.23 17.46,85.09 | 17.46,85.09 IC2.4 | v6.67,52.39 6.67,51.22 R59.1 5.5,51.12 C24.1 | v17.14,36.51 17.46,36.2 17.46,35.34 C32.1 17.46,35.14 17.46,31.75 | IC10.16 C36.1 23.28,28.16 22.86,28.57 20.64,28.57 v20.32,28.89 17.46,31.75 | 17.46,31.75 IC9.4 | IC12.4 17.14,7.94 17.78,7.3 17.78,4.55 C46.1 17.78,4.34 v17.78,3.17 | IC8.4 49.53,36.83 50.06,37.36 C30.1 50.16,40.42 50.16,43.34 51.44,44.61 v54.29,44.61 | IC11.4 49.53,10.16 50.06,10.69 C43.1 50.16,13.76 50.16,16.51 51.44,17.78 v54.29,17.78 | v10.16,26.99 R86.1 | v10.16,80.33 R25.1
  Top 0.406: v54.93,101.76 54.61,102.08 38.1,102.08 35.72,99.69 33.34,99.69 31.11,97.47 6.67,97.47 6.03,96.84 v6.03,96.2 | 4.76,97.47 1.59,94.3 1.59,90.65 v1.91,90.33 1.91,67.63 1.59,67.31 1.59,65.41 1.91,65.09 v1.91,54.93 v1.91,52.39 1.91,40.96 1.59,40.64 1.59,37.31 v1.91,36.99 1.91,14.29 1.59,13.97 1.59,12.06 2.86,10.79 2.86,4.45 v2.54,4.13 | 4.76,97.47 6.99,99.69 C2.+ 8.08,100.19 9.21,99.06 L1.1 | 4.76,97.47 v4.45,97.79
  Bottom 0.254: 55.24,97.95 v54.29,97.95 | 55.24,71.28 v54.29,71.28 | v17.14,89.85 16.19,90.81 3.65,90.81 3.17,90.33 v1.91,90.33 | v17.78,56.52 16.19,54.93 v1.91,54.93 | v1.91,52.39 v6.67,52.39 | v17.14,36.51 16.19,37.47 3.65,37.47 3.17,36.99 v1.91,36.99 | v17.78,3.17 16.83,2.22 6.67,2.22 4.76,4.13 v2.54,4.13 | 55.24,44.61 v54.29,44.61 | v10.16,26.99 15.24,26.99 17.14,28.89 v20.32,28.89 | v10.16,80.33 15.24,80.33 17.14,82.23 v20.32,82.23
  Bottom 0.406: v54.93,101.76 55.24,101.44 55.24,97.95 55.24,96.2 54.93,95.89 54.93,94.77 55.24,94.46 55.24,71.28 55.24,69.69 54.93,69.37 54.93,68.1 55.24,67.79 55.24,44.61 55.24,43.02 54.93,42.7 54.93,41.43 55.24,41.12 55.24,18.73 v54.29,17.78 | v4.45,97.79 v6.03,96.2
VEE  (via drill 0.5)
  Top 0.254: IC3.9 22.23,72.07 22.86,72.71 | 22.86,72.71 C16.2 | IC1.11 52.39,90.17 51.91,89.69 51.12,89.69 50.64,90.17 50.64,92.23 51.12,92.71 52.86,92.71 53.34,93.19 55.4,93.19 55.78,93.56 C4.2 55.88,94.24 v55.88,95.41 | 50.64,65.72 50.96,66.04 52.7,66.04 53.18,66.52 55.4,66.52 55.88,66.99 55.88,67.37 C17.2 55.88,67.57 v55.88,68.74 | 50.64,65.72 | 50.64,65.72 50.64,63.66 51.12,63.18 52.23,63.18 52.55,63.5 IC4.11 | 22.86,72.71 23.18,72.39 v23.18,71.44 | v10.79,53.02 11.75,52.07 13.02,52.07 13.34,51.75 13.34,51.22 R60.1 14.5,51.12 C25.1 | 19.37,36.2 v19.68,36.51 19.05,35.88 19.05,35.34 C33.2 19.15,32.6 20,31.75 IC9.11 | C47.2 19.05,4.55 | IC10.9 22.23,18.73 22.86,19.37 C41.2 23.18,19.27 v23.18,17.78 | 2.54,17.46 v3.17,17.46 | v19.05,56.52 19.05,57.68 C22.2 19.15,58.16 19.05,58.26 19.05,59.69 18.73,60.01 18.73,60.64 19.37,61.28 IC5.11 | C47.2 19.05,4.34 v19.05,3.17 | v55.88,42.07 55.88,40.9 C29.2 55.78,40.38 55.24,39.85 55.09,39.85 | 55.09,39.85 53.18,39.85 52.7,39.37 51.12,39.37 50.64,38.89 50.64,36.67 51.12,36.2 51.75,36.2 52.39,36.83 IC8.11 | 55.09,39.85 | IC11.11 53.02,10.16 52.7,10.48 52.7,12.7 54.08,14.07 C42.2 54.08,15.66 v55.24,16.83 | v19.68,89.85 19.15,89.32 C8.2 19.15,85.78 19.84,85.09 IC2.11 | IC12.11 19.37,7.94 18.73,7.3 18.73,6.03 19.15,5.61 C47.2
  Top 0.406: 2.54,71.12 2.54,67.31 2.22,66.99 2.22,65.72 2.54,65.41 2.54,55.88 2.86,55.56 v2.86,53.98 2.86,51.12 2.54,50.8 2.54,40.64 2.22,40.32 2.22,38.58 v2.86,37.94 2.86,36.51 2.54,36.2 2.54,17.46 2.54,13.97 2.22,13.65 2.22,12.38 3.49,11.11 v3.49,3.17 | 2.54,71.12 v3.17,71.12 | 2.54,71.12 2.54,89.53 2.86,89.85 v2.86,91.28 2.22,91.92 2.22,93.98 6.35,98.11 30.48,98.11 30.8,98.42 30.8,99.06 | 30.8,99.06 L2.1 | 30.8,99.06 30.8,99.69 | 30.8,99.69 C1.- | 30.8,99.69 32.07,99.69 33.34,100.97 D1.A 35.88,100.97 37.62,102.71 v55.88,102.71
  Bottom 0.254: 18.26,91.28 v19.68,89.85 | v23.18,71.44 22.86,71.12 v3.17,71.12 | v19.05,56.52 16.83,54.29 10.79,54.29 | v2.86,53.98 3.17,54.29 10.79,54.29 | 10.79,54.29 v10.79,53.02 | v23.18,17.78 22.86,17.46 v3.17,17.46 | v19.05,3.17 17.46,1.59 6.35,1.59 4.76,3.17 v3.49,3.17 | 18.26,91.28 | v2.86,91.28 18.26,91.28 | v19.68,36.51 18.26,37.94 v2.86,37.94
  Bottom 0.406: v55.88,102.71 v55.88,95.41 v55.88,68.74 v55.88,42.07 55.88,17.46 v55.24,16.83

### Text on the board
bPlace: stripe | Red
tNames: Blinds | cc-by-sa Émilie Gillet, | 2015. v6
bNames: +12V | GND | -12V | Blinds | cc-by-sa Émilie Gillet, | 2015. v6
